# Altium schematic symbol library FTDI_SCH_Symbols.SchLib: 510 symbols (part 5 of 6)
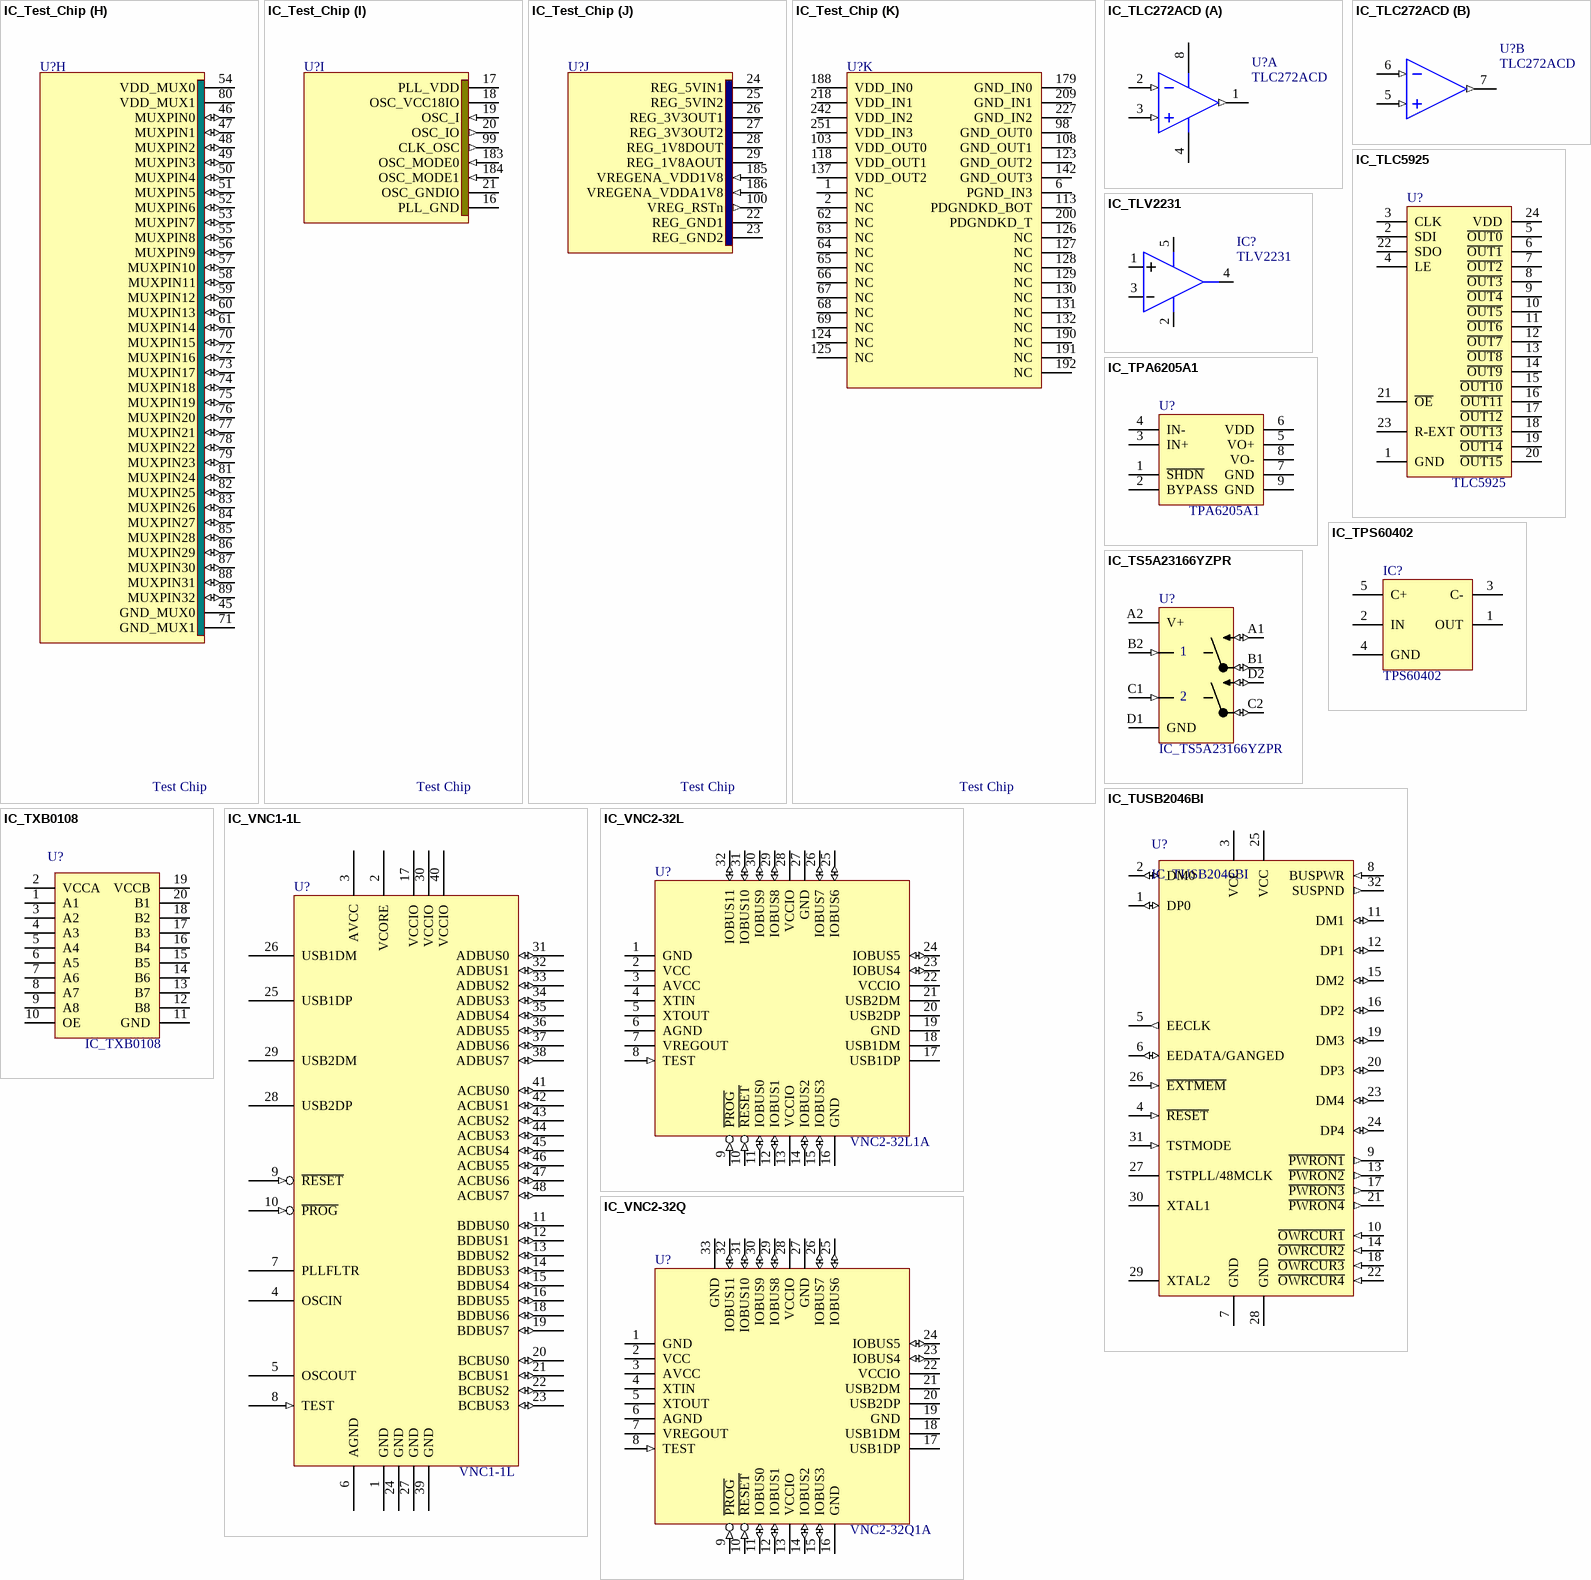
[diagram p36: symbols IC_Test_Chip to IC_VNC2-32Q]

## IC_Test_Chip
designator U?, comment Test Chip
part A pins: 97 SCAN_MODE, 181 CLK_SYS, 182 RST#
part B pins: 90 GND_USB110_L (power), 91 USB1_DP (io), 92 USB1_DM (io), 93 VCCUSB110_SH (power), 94 USB0_DP (io), 95 USB0_DM (io), 96 GNDUSB110_R (power)
part C pins: 30 VDD_USB230_T (power), 31 GND_USB230_T (power), 32 USB230_XSCI (in), 33 USB230_XSCO (out), 34 USB230_VCCHSRT1 (power), 35 USB230_VCCHSRT2 (power), 36 USB230_GNDHSRT1 (power), 37 USB230_GNDHSRT2 (power), 38 USB230_RREF (in), 39 USB230_DM (io), 40 USB230_DP (io), 41 USB230_VCCA_U20 (power), 42 USB230_GNDA_U20 (power), 43 GND_USB230_B (power), 44 VCC_USB230_B (power), 140 USBHS_CLKOUT (out), 141 USBHS_TXREADY (out), 143 USBHS_RXVALID (out), 144 USBHS_RXACTIVE (out), 145 USBHS_RXERR (out), 146 USBHS_HOSTDISC (out), 147 USBHS_PORSIG (out), 187 USB_HS_SEL (in)
part D pins: 101 EE_DONEX (out), 102 EE_DOX0 (out), 104 EE_DOX1 (out), 105 EE_DOX2 (out), 106 EE_DOX3 (out), 107 EE_DOX4 (out), 109 EE_DOX5 (out), 110 EE_DOX6 (out), 111 EE_DOX7 (out), 112 EE_DOX8 (out), 114 EE_DOX9 (out), 115 EE_DOX10 (out), 116 EE_DOX11 (out), 189 EE_SEL (in), 193 EE_CLKX (in), 194 EE_MODEX0 (in), 195 EE_MODEX1 (in), 196 EE_MODEX2 (in), 197 EE_GOX (in), 198 EE_EXTENDX (in), 199 EE_RSTNX (in), 201 EE_PAGE_ADDRX0 (in), 202 EE_PAGE_ADDRX1 (in), 203 EE_PAGE_ADDRX2 (in), 204 EE_PAGE_ADDRX3 (in), 205 EE_PAGE_ADDRX4 (in), 206 EE_PAGE_ADDRX5 (in), 207 EE_PAGE_ADDRX6 (in), 208 EE_BYTE_ADDRX0 (in), 210 EE_BYTE_ADDRX1 (in), 211 EE_BIT_ADDRX0 (in), 212 EE_BIT_ADDRX1 (in), 213 EE_BIT_ADDRX2 (in), 214 EE_BIT_ADDRX3 (in), 215 EE_DINX (in), 216 EE_SA_BIAS0 (in), 217 EE_SA_BIAS1 (in), 219 EE_SA_BIAS2 (in), 220 EE_SA_BIAS3 (in), 221 EE_SA_BIAS_ONX (in), 228 VPP_EE0, 229 VDD3V3_EE0, 230 VDD1V8_EE0, 239 GND_EE, 240 VDD3V3_EE1, 241 VDD1V8_EE1
part E pins: 3 HADDR7 (in), 4 HWD0 (in), 5 HWD1 (in), 7 HWD2 (in), 8 HWD3 (in), 9 HWD4 (in), 10 HWD5 (in), 11 HWD6 (in), 12 HWD7 (in), 13 HWRITE (in), 14 HREADY (in), 15 HSEL_IOCTRL (in), 121 HRD0 (in), 122 HRD1 (in), 133 HRD2 (in), 134 HRD3 (in), 135 HRD4 (in), 136 HRD5 (in), 138 HRD6 (in), 139 HRD7 (in), 180 HSEL_PADCTRL (in), 249 HADDR0 (in), 250 HADDR1 (in), 252 HADDR2 (in), 253 HADDR3 (in), 254 HADDR4 (in), 255 HADDR5 (in), 256 HADDR6 (in)
part F pins: 120 IOCELLCONTR_INT, 148 IOPBOND0 (io), 149 IOPBOND1 (io), 150 IOPBOND2 (io), 151 IOPBOND3 (io), 152 GND_PADUNI2 (power), 153 IOPBOND4 (io), 154 IOPBOND5 (io), 155 IOPBOND6 (io), 156 IOPBOND7 (io), 157 VDD_PADUNI2 (power), 158 IOPBOND8 (io), 159 IOPBOND9 (io), 160 IOPBOND10 (io), 161 IOPBOND11 (io), 162 GND_PADUNI1 (power), 163 IOPBOND12 (io), 164 IOPBOND13 (io), 165 IOPBOND14 (io), 166 IOPBOND15 (io), 167 VDD_PADUNI1 (power), 168 IOPBOND16 (io), 169 IOPBOND17 (io), 170 IOPBOND18 (io), 171 IOPBOND19 (io), 172 GND_PADUNI0 (power), 173 IOPBOND20 (io), 174 IOPBOND21 (io), 175 IOPBOND22 (io), 176 IOPBOND23 (io), 177 VDD_PADUNI0 (power), 178 IOBOND_SINGLE (io)
part G pins: 117 IOP_SINGLE_DIN (out), 119 IOP_SINGLE_CMPOUT (out), 222 IOP_SINGLE_DAC_D0 (in), 223 IOP_SINGLE_DAC_D1 (in), 224 IOP_SINGLE_DAC_D2 (in), 225 IOP_SINGLE_DAC_D3 (in), 226 IOP_SINGLE_DAC_D4 (in), 231 IOP_SINGLE_DAC_D5 (in), 232 IOP_SINGLE_DAC_D6 (in), 233 IOP_SINGLE_DAC_D7 (in), 234 IOP_SINGLE_DAC_D8 (in), 235 IOP_SINGLE_DAC_D9 (in), 236 IOP_SINGLE_DOUT (in), 237 IOP_SINGLE_DMODE0 (in), 238 IOP_SINGLE_DMODE1 (in), 243 IOP_SINGLE_DIENA (in), 244 IOP_SINGLE_PUENAn (in), 245 IOP_SINGLE_PDENA (in), 246 IOP_SINGLE_SAMPLE (in), 247 IOP_SINGLE_AMODE0 (in), 248 IOP_SINGLE_AMODE1 (in)
part H pins: 45 GND_MUX0 (power), 46 MUXPIN0 (io), 47 MUXPIN1 (io), 48 MUXPIN2 (io), 49 MUXPIN3 (io), 50 MUXPIN4 (io), 51 MUXPIN5 (io), 52 MUXPIN6 (io), 53 MUXPIN7 (io), 54 VDD_MUX0 (power), 55 MUXPIN8 (io), 56 MUXPIN9 (io), 57 MUXPIN10 (io), 58 MUXPIN11 (io), 59 MUXPIN12 (io), 60 MUXPIN13 (io), 61 MUXPIN14 (io), 70 MUXPIN15 (io), 71 GND_MUX1 (power), 72 MUXPIN16 (io), 73 MUXPIN17 (io), 74 MUXPIN18 (io), 75 MUXPIN19 (io), 76 MUXPIN20 (io), 77 MUXPIN21 (io), 78 MUXPIN22 (io), 79 MUXPIN23 (io), 80 VDD_MUX1 (power), 81 MUXPIN24 (io), 82 MUXPIN25 (io), 83 MUXPIN26 (io), 84 MUXPIN27 (io), 85 MUXPIN28 (io), 86 MUXPIN29 (io), 87 MUXPIN30 (io), 88 MUXPIN31 (io), 89 MUXPIN32 (io)
part I pins: 16 PLL_GND (power), 17 PLL_VDD (power), 18 OSC_VCC18IO (power), 19 OSC_I (in), 20 OSC_IO (out), 21 OSC_GNDIO (power), 99 CLK_OSC (out), 183 OSC_MODE0 (in), 184 OSC_MODE1 (in)
part J pins: 22 REG_GND1 (power), 23 REG_GND2 (power), 24 REG_5VIN1 (power), 25 REG_5VIN2 (power), 26 REG_3V3OUT1 (power), 27 REG_3V3OUT2 (power), 28 REG_1V8DOUT (power), 29 REG_1V8AOUT (power), 100 VREG_RSTn (out), 185 VREGENA_VDD1V8 (in), 186 VREGENA_VDDA1V8 (in)
part K pins: 1 NC, 2 NC, 6 PGND_IN3 (power), 62 NC, 63 NC, 64 NC, 65 NC, 66 NC, 67 NC, 68 NC, 69 NC, 98 GND_OUT0 (power), 103 VDD_OUT0 (power), 108 GND_OUT1 (power), 113 PDGNDKD_BOT (power), 118 VDD_OUT1 (power), 123 GND_OUT2 (power), 124 NC, 125 NC, 126 NC, 127 NC, 128 NC, 129 NC, 130 NC, 131 NC, 132 NC, 137 VDD_OUT2 (power), 142 GND_OUT3 (power), 179 GND_IN0, 188 VDD_IN0 (power), 190 NC, 191 NC, 192 NC, 200 PDGNDKD_T (power), 209 GND_IN1 (power), 218 VDD_IN1 (power), 227 GND_IN2 (power), 242 VDD_IN2 (power), 251 VDD_IN3 (power)

## IC_TLC272ACD
designator U?, comment TLC272ACD
LinCMOS Precision Dual Operational Amplifier
3D model D008 (8-Pin Small Outline Integrated Circuit 1.27 mm Pitch)
footprint SO-8_N (8-Pin Small Outline Integrated Circuit 1.27 mm Pitch, IPC Medium Density)
part A pins: 1 OUT (out), 2 IN- (in), 3 IN+ (in), 4 VDD-, 8 VDD+
part B pins: 5 IN+ (in), 6 IN- (in), 7 OUT (out)

## IC_TLC5925
designator U?, comment TLC5925
LOW-POWER 16-CHANNEL CONSTANT-CURRENT LED SINK DRIVER
footprint SO-24N (SOIC, 24-Leads, Body 15.4x7.5mm, Pitch 1.27mm, IPC Medium Density)
footprint TSOP65P640X120-24N (TSOP, 24-Leads, Body 7.9x4.5mm (max), Pitch 0.65mm, IPC Medium Density)
pins: 1 GND, 2 SDI, 3 CLK, 4 LE, 5 ~{OUT0}, 6 ~{OUT1}, 7 ~{OUT2}, 8 ~{OUT3}, 9 ~{OUT4}, 10 ~{OUT5}, 11 ~{OUT6}, 12 ~{OUT7}, 13 ~{OUT8}, 14 ~{OUT9}, 15 ~{OUT10}, 16 ~{OUT11}, 17 ~{OUT12}, 18 ~{OUT13}, 19 ~{OUT14}, 20 ~{OUT15}, 21 ~{OE}, 22 SDO, 23 R-EXT, 24 VDD

## IC_TLV2231
designator IC?, comment TLV2231
Single operational amplifier
footprint SOT23-5AL (SOT23, 5-Leads, Body 2.9x1.6mm, Pitch 0.95mm, Lead Span 2.8mm, IPC High Density)
pins: 1 IN+, 2 V-, 3 IN-, 4 OUT, 5 V+

## IC_TPA6205A1
designator U?, comment TPA6205A1
IC AMP AUDIO PWR 1.25W AB 8MSOP; ManufacturerPartNo: TPA6205A1DGNR; Manufacturer: TI
footprint PSO06531x505-8N
pins: 1 ~{SHDN}, 2 BYPASS, 3 IN+, 4 IN-, 5 VO+, 6 VDD, 7 GND, 8 VO-, 9 GND

## IC_TPS60402
designator IC?, comment TPS60402
Voltage inverter
footprint SOT23-5AL (SOT23, 5-Leads, Body 2.9x1.6mm, Pitch 0.95mm, Lead Span 2.8mm, IPC High Density)
pins: 1 OUT, 2 IN, 3 C-, 4 GND (power), 5 C+

## IC_TS5A23166YZPR
designator U?
0.9-OHM 5-V/3.3-V 2-CHANNEL ANALOG SWITCH
footprint BGA8C50P4X2_190X90X50 (BGA, 8-Leads, Body 1.9x0.9mm,  Pitch 0.50mm)
pins: A1 NO1 (io), A2 V+ (power), B1 COM1 (io), B2 IN1 (in), C1 IN2 (in), C2 COM2 (io), D1 GND (power), D2 NO2 (io)

## IC_TUSB2046BI
designator U?
4 Port USB HUB
footprint TQFP80P900X900X160-32N (TQFP, 32-Leads, Body 9.2x9.2mm (max), Pitch 0.80mm, IPC Medium Density)
pins: 1 DP0 (io), 2 DM0 (io), 3 VCC (power), 4 ~{RESET} (in), 5 EECLK (out), 6 EEDATA/GANGED (io), 7 GND (power), 8 BUSPWR (in), 9 ~{PWRON1} (out), 10 ~{OWRCUR1} (in), 11 DM1 (io), 12 DP1 (io), 13 ~{PWRON2} (out), 14 ~{OWRCUR2} (in), 15 DM2 (io), 16 DP2 (io), 17 ~{PWRON3} (out), 18 ~{OWRCUR3} (in), 19 DM3 (io), 20 DP3 (io), 21 ~{PWRON4} (out), 22 ~{OWRCUR4} (in), 23 DM4 (io), 24 DP4 (io), 25 VCC (power), 26 ~{EXTMEM} (in), 27 TSTPLL/48MCLK, 28 GND (power), 29 XTAL2, 30 XTAL1, 31 TSTMODE (in), 32 SUSPND (out)

## IC_TXB0108
designator U?
8-BIT BIDIRECTIONAL VOLTAGE-LEVEL TRANSLATOR  WITH AUTO-DIRECTION SENSING AND ±15-kV ESD PROTECTION
footprint TSOP65P640X120-20N (TSOP, 20-Leads, Body 6.6x4.5mm (max), Pitch 0.65mm, IPC Medium Density)
pins: 1 A1, 2 VCCA, 3 A2, 4 A3, 5 A4, 6 A5, 7 A6, 8 A7, 9 A8, 10 OE, 11 GND, 12 B8, 13 B7, 14 B6, 15 B5, 16 B4, 17 B3, 18 B2, 19 VCCB, 20 B1

## IC_VNC1-1L
designator U?, comment VNC1-1L
footprint LQFP-48_N (48-Pin Thin Quad Flat Pack 0.5 mm Pitch, IPC Medium Density)
pins: 1 GND (power), 2 VCORE (power), 3 AVCC (power), 4 OSCIN, 5 OSCOUT, 6 AGND (power), 7 PLLFLTR, 8 TEST (in), 9 ~{RESET} (in), 10 ~{PROG} (in), 11 BDBUS0 (io), 12 BDBUS1 (io), 13 BDBUS2 (io), 14 BDBUS3 (io), 15 BDBUS4 (io), 16 BDBUS5 (io), 17 VCCIO (power), 18 BDBUS6 (io), 19 BDBUS7 (io), 20 BCBUS0 (io), 21 BCBUS1 (io), 22 BCBUS2 (io), 23 BCBUS3 (io), 24 GND (power), 25 USB1DP, 26 USB1DM, 27 GND (power), 28 USB2DP, 29 USB2DM, 30 VCCIO (power), 31 ADBUS0 (io), 32 ADBUS1 (io), 33 ADBUS2 (io), 34 ADBUS3 (io), 35 ADBUS4 (io), 36 ADBUS5 (io), 37 ADBUS6 (io), 38 ADBUS7 (io), 39 GND (power), 40 VCCIO (power), 41 ACBUS0 (io), 42 ACBUS1 (io), 43 ACBUS2 (io), 44 ACBUS3 (io), 45 ACBUS4 (io), 46 ACBUS5 (io), 47 ACBUS6 (io), 48 ACBUS7 (io)

## IC_VNC2-32L
designator U?, comment VNC2-32L1A
Vinculum-II Embedded USB Host Controller IC; 32 pin LQFP
footprint LQFP-32_N (32-Pin Thin Quad Flat Pack 0.8 mm Pitch, IPC Medium Density)
pins: 1 GND (power), 2 VCC (power), 3 AVCC (power), 4 XTIN, 5 XTOUT, 6 AGND (power), 7 VREGOUT (power), 8 TEST (in), 9 ~{PROG} (in), 10 ~{RESET} (in), 11 IOBUS0 (io), 12 IOBUS1 (io), 13 VCCIO (power), 14 IOBUS2 (io), 15 IOBUS3 (io), 16 GND (power), 17 USB1DP, 18 USB1DM, 19 GND (power), 20 USB2DP, 21 USB2DM, 22 VCCIO (power), 23 IOBUS4 (io), 24 IOBUS5 (io), 25 IOBUS6 (io), 26 IOBUS7 (io), 27 GND (power), 28 VCCIO (power), 29 IOBUS8 (io), 30 IOBUS9 (io), 31 IOBUS10 (io), 32 IOBUS11 (io)

## IC_VNC2-32Q
designator U?, comment VNC2-32Q1A
Vinculum-II Embedded USB Host Controller IC; 32 pin QFN
footprint QFN32_N (32-Pin Quad Flat No-Lead 0.5 mm Pitch, IPC Medium Density)
pins: 1 GND (power), 2 VCC (power), 3 AVCC (power), 4 XTIN, 5 XTOUT, 6 AGND (power), 7 VREGOUT (power), 8 TEST (in), 9 ~{PROG} (in), 10 ~{RESET} (in), 11 IOBUS0 (io), 12 IOBUS1 (io), 13 VCCIO (power), 14 IOBUS2 (io), 15 IOBUS3 (io), 16 GND (power), 17 USB1DP, 18 USB1DM, 19 GND (power), 20 USB2DP, 21 USB2DM, 22 VCCIO (power), 23 IOBUS4 (io), 24 IOBUS5 (io), 25 IOBUS6 (io), 26 IOBUS7 (io), 27 GND (power), 28 VCCIO (power), 29 IOBUS8 (io), 30 IOBUS9 (io), 31 IOBUS10 (io), 32 IOBUS11 (io), 33 GND (power)

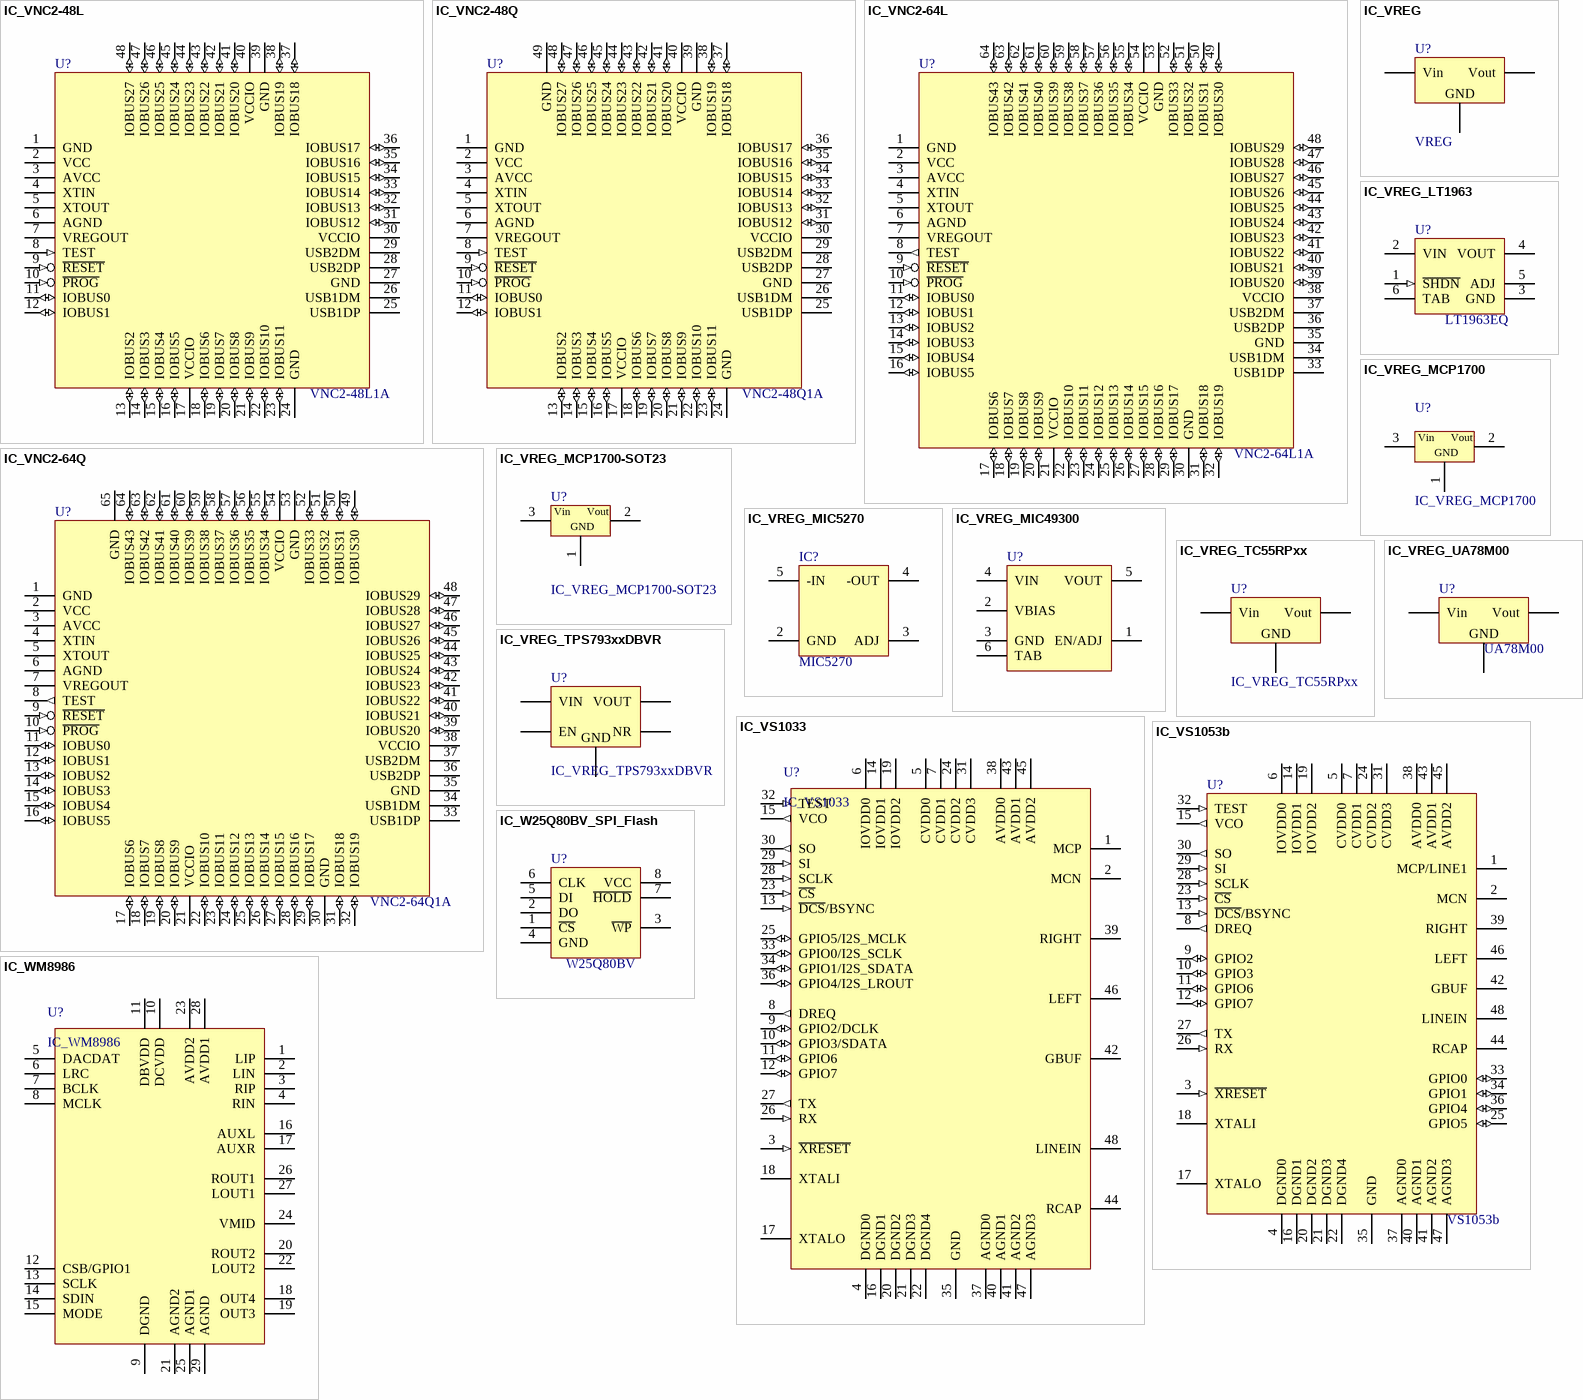
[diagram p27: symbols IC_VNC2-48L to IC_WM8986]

## IC_VNC2-48L
designator U?, comment VNC2-48L1A
Vinculum-II Embedded USB Host Controller IC; 48-pin LQFP
footprint LQFP-48_N (48-Pin Thin Quad Flat Pack 0.5 mm Pitch, IPC Medium Density)
pins: 1 GND (power), 2 VCC (power), 3 AVCC (power), 4 XTIN, 5 XTOUT, 6 AGND (power), 7 VREGOUT (power), 8 TEST (in), 9 ~{RESET} (in), 10 ~{PROG} (in), 11 IOBUS0 (io), 12 IOBUS1 (io), 13 IOBUS2 (io), 14 IOBUS3 (io), 15 IOBUS4 (io), 16 IOBUS5 (io), 17 VCCIO (power), 18 IOBUS6 (io), 19 IOBUS7 (io), 20 IOBUS8 (io), 21 IOBUS9 (io), 22 IOBUS10 (io), 23 IOBUS11 (io), 24 GND (power), 25 USB1DP, 26 USB1DM, 27 GND (power), 28 USB2DP, 29 USB2DM, 30 VCCIO (power), 31 IOBUS12 (io), 32 IOBUS13 (io), 33 IOBUS14 (io), 34 IOBUS15 (io), 35 IOBUS16 (io), 36 IOBUS17 (io), 37 IOBUS18 (io), 38 IOBUS19 (io), 39 GND (power), 40 VCCIO (power), 41 IOBUS20 (io), 42 IOBUS21 (io), 43 IOBUS22 (io), 44 IOBUS23 (io), 45 IOBUS24 (io), 46 IOBUS25 (io), 47 IOBUS26 (io), 48 IOBUS27 (io)

## IC_VNC2-48Q
designator U?, comment VNC2-48Q1A
Vinculum-II Embedded USB Host Controller IC; 48-pin QFN
footprint QFN50P800X800-48N (QFN, 48-Leads, Body 8.0x8.0mm (max), Pitch 0.50mm, IPC Medium Density)
pins: 1 GND (power), 2 VCC (power), 3 AVCC (power), 4 XTIN, 5 XTOUT, 6 AGND (power), 7 VREGOUT (power), 8 TEST (in), 9 ~{RESET} (in), 10 ~{PROG} (in), 11 IOBUS0 (io), 12 IOBUS1 (io), 13 IOBUS2 (io), 14 IOBUS3 (io), 15 IOBUS4 (io), 16 IOBUS5 (io), 17 VCCIO (power), 18 IOBUS6 (io), 19 IOBUS7 (io), 20 IOBUS8 (io), 21 IOBUS9 (io), 22 IOBUS10 (io), 23 IOBUS11 (io), 24 GND (power), 25 USB1DP, 26 USB1DM, 27 GND (power), 28 USB2DP, 29 USB2DM, 30 VCCIO (power), 31 IOBUS12 (io), 32 IOBUS13 (io), 33 IOBUS14 (io), 34 IOBUS15 (io), 35 IOBUS16 (io), 36 IOBUS17 (io), 37 IOBUS18 (io), 38 IOBUS19 (io), 39 GND (power), 40 VCCIO (power), 41 IOBUS20 (io), 42 IOBUS21 (io), 43 IOBUS22 (io), 44 IOBUS23 (io), 45 IOBUS24 (io), 46 IOBUS25 (io), 47 IOBUS26 (io), 48 IOBUS27 (io), 49 GND (power)

## IC_VNC2-64L
designator U?, comment VNC2-64L1A
Vinculum-II Embedded USB Host Controller IC; 64-pin LQFP
footprint LQFP50P10X10-64N (LQFP, 64-Leads, Body 10x10mm (max), Pitch 0.50mm, IPC Medium Density)
pins: 1 GND (power), 2 VCC (power), 3 AVCC (power), 4 XTIN, 5 XTOUT, 6 AGND (power), 7 VREGOUT (power), 8 TEST (out), 9 ~{RESET} (in), 10 ~{PROG} (in), 11 IOBUS0 (io), 12 IOBUS1 (io), 13 IOBUS2 (io), 14 IOBUS3 (io), 15 IOBUS4 (io), 16 IOBUS5 (io), 17 IOBUS6 (io), 18 IOBUS7 (io), 19 IOBUS8 (io), 20 IOBUS9 (io), 21 VCCIO (power), 22 IOBUS10 (io), 23 IOBUS11 (io), 24 IOBUS12 (io), 25 IOBUS13 (io), 26 IOBUS14 (io), 27 IOBUS15 (io), 28 IOBUS16 (io), 29 IOBUS17 (io), 30 GND (power), 31 IOBUS18 (io), 32 IOBUS19 (io), 33 USB1DP, 34 USB1DM, 35 GND (power), 36 USB2DP, 37 USB2DM, 38 VCCIO (power), 39 IOBUS20 (io), 40 IOBUS21 (io), 41 IOBUS22 (io), 42 IOBUS23 (io), 43 IOBUS24 (io), 44 IOBUS25 (io), 45 IOBUS26 (io), 46 IOBUS27 (io), 47 IOBUS28 (io), 48 IOBUS29 (io), 49 IOBUS30 (io), 50 IOBUS31 (io), 51 IOBUS32 (io), 52 IOBUS33 (io), 53 GND (power), 54 VCCIO (power), 55 IOBUS34 (io), 56 IOBUS35 (io), 57 IOBUS36 (io), 58 IOBUS37 (io), 59 IOBUS38 (io), 60 IOBUS39 (io), 61 IOBUS40 (io), 62 IOBUS41 (io), 63 IOBUS42 (io), 64 IOBUS43 (io)

## IC_VNC2-64Q
designator U?, comment VNC2-64Q1A
Vinculum-II Embedded USB Host Controller IC; 64-pin QFN
footprint QFN50P900X900-64N (QFN, 64-Leads, Body 9x9mm, Pitch 0.50mm, IPC Medium Density)
pins: 1 GND (power), 2 VCC (power), 3 AVCC (power), 4 XTIN, 5 XTOUT, 6 AGND (power), 7 VREGOUT (power), 8 TEST (out), 9 ~{RESET} (in), 10 ~{PROG} (in), 11 IOBUS0 (io), 12 IOBUS1 (io), 13 IOBUS2 (io), 14 IOBUS3 (io), 15 IOBUS4 (io), 16 IOBUS5 (io), 17 IOBUS6 (io), 18 IOBUS7 (io), 19 IOBUS8 (io), 20 IOBUS9 (io), 21 VCCIO (power), 22 IOBUS10 (io), 23 IOBUS11 (io), 24 IOBUS12 (io), 25 IOBUS13 (io), 26 IOBUS14 (io), 27 IOBUS15 (io), 28 IOBUS16 (io), 29 IOBUS17 (io), 30 GND (power), 31 IOBUS18 (io), 32 IOBUS19 (io), 33 USB1DP, 34 USB1DM, 35 GND (power), 36 USB2DP, 37 USB2DM, 38 VCCIO (power), 39 IOBUS20 (io), 40 IOBUS21 (io), 41 IOBUS22 (io), 42 IOBUS23 (io), 43 IOBUS24 (io), 44 IOBUS25 (io), 45 IOBUS26 (io), 46 IOBUS27 (io), 47 IOBUS28 (io), 48 IOBUS29 (io), 49 IOBUS30 (io), 50 IOBUS31 (io), 51 IOBUS32 (io), 52 IOBUS33 (io), 53 GND (power), 54 VCCIO (power), 55 IOBUS34 (io), 56 IOBUS35 (io), 57 IOBUS36 (io), 58 IOBUS37 (io), 59 IOBUS38 (io), 60 IOBUS39 (io), 61 IOBUS40 (io), 62 IOBUS41 (io), 63 IOBUS42 (io), 64 IOBUS43 (io), 65 GND (power)

## IC_VREG
designator U?, comment VREG
Voltage Regulator
footprint SOT223P700-4N (SOT223, 4-Leads, Body 6.5x3.5mm, Pitch 2.3mm, Lead Span 7mm, IPC Medium Density)
footprint TO228P973X240-3N (D-PAK, 3-Pads, Body 6.2x6.6mm (max), IPC Medium Density)
pins: 1 GND, 3 Vin, 4 Vout

## IC_VREG_LT1963
designator U?, comment LT1963EQ
1.5A, Low Noise,  Fast Transient Response  LDO Regulator
pins: 1 ~{SHDN} (in), 2 VIN (power), 3 GND (power), 4 VOUT (power), 5 ADJ, 6 TAB (power)

## IC_VREG_MCP1700
designator U?
LDO Vlotage Regulator
footprint SOT23-3AL (SOT23 SMT Package)
pins: 1 GND, 2 Vout, 3 Vin

## IC_VREG_MCP1700-SOT23
designator U?
Voltage Regulator
footprint SOT23-3AL (SOT23 SMT Package)
pins: 1 GND, 2 Vout, 3 Vin

## IC_VREG_MIC5270
designator IC?, comment MIC5270
footprint SOT23-5AL (SOT23, 5-Leads, Body 2.9x1.6mm, Pitch 0.95mm, Lead Span 2.8mm, IPC High Density)
pins: 2 GND (power), 3 ADJ, 4 -OUT, 5 -IN

## IC_VREG_MIC49300
designator U?
3.0A Low Voltage LDO Regulator w/Dual Input Voltages; Micrel
pins: 1 EN/ADJ, 2 VBIAS, 3 GND, 4 VIN, 5 VOUT, 6 TAB

## IC_VREG_TC55RPxx
designator U?
1uA LOW DROPOUT POSITIVE VOLTAGE REGULATOR
footprint SOT23-3AL (SOT23 SMT Package)
pins: 1 GND, 2 Vout, 3 Vin

## IC_VREG_TPS793xxDBVR
designator U?
LDO Voltage Regulator; 1.5A; DPAK-3
footprint SOT23-5AL (SOT23, 5-Leads, Body 2.9x1.6mm, Pitch 0.95mm, Lead Span 2.8mm)
pins: 1 VIN, 2 GND, 3 EN, 4 NR, 5 VOUT

## IC_VREG_UA78M00
designator U?, comment UA78M00
0.5A Voltage Regulator
footprint SOT223P700X180-4N (SOT223, 4-Leads, Body 6.7x7.3mm (max), Pitch 2.30mm, IPC Medium Density)
footprint TO252P955X203-3N (D-PAK, 3-Pads, Body 6.3x6.2mm (max), IPC Medium Density); pin to pad 2>4 4>2
pins: 1 Vin, 2 Vout, 3 GND, 4 Vout hidden

## IC_VS1033
designator U?
single-chip MP3/AAC/WMA/MIDI  audio decoder and ADPCM encoder; VLSI Solution Oy
footprint LQFP-48_N (48-Pin Thin Quad Flat Pack 0.5 mm Pitch, IPC Medium Density)
pins: 1 MCP, 2 MCN, 3 ~{XRESET} (in), 4 DGND0 (power), 5 CVDD0 (power), 6 IOVDD0 (power), 7 CVDD1 (power), 8 DREQ (out), 9 GPIO2/DCLK (io), 10 GPIO3/SDATA (io), 11 GPIO6 (io), 12 GPIO7 (io), 13 ~{DCS}/BSYNC (in), 14 IOVDD1 (power), 15 VCO (out), 16 DGND1 (power), 17 XTALO, 18 XTALI, 19 IOVDD2 (power), 20 DGND2 (power), 21 DGND3 (power), 22 DGND4 (power), 23 ~{CS} (in), 24 CVDD2 (power), 25 GPIO5/I2S_MCLK (io), 26 RX (in), 27 TX (out), 28 SCLK (in), 29 SI (in), 30 SO (out), 31 CVDD3 (power), 32 TEST (in), 33 GPIO0/I2S_SCLK (io), 34 GPIO1/I2S_SDATA (io), 35 GND (power), 36 GPIO4/I2S_LROUT (io), 37 AGND0 (power), 38 AVDD0 (power), 39 RIGHT, 40 AGND1 (power), 41 AGND2 (power), 42 GBUF, 43 AVDD1 (power), 44 RCAP, 45 AVDD2 (power), 46 LEFT, 47 AGND3 (power), 48 LINEIN

## IC_VS1053b
designator U?, comment VS1053b
Single-chip Ogg Vorbis/MP3/AAC/-  WMA/MIDI audio decoder and an IMA ADPCM  and user-loadable Ogg Vorbis encoder.; VLSI Solution Oy
footprint LQFP-48_N (48-Pin Thin Quad Flat Pack 0.5 mm Pitch, IPC Medium Density)
pins: 1 MCP/LINE1, 2 MCN, 3 ~{XRESET} (in), 4 DGND0 (power), 5 CVDD0 (power), 6 IOVDD0 (power), 7 CVDD1 (power), 8 DREQ (out), 9 GPIO2 (io), 10 GPIO3 (io), 11 GPIO6 (io), 12 GPIO7 (io), 13 ~{DCS}/BSYNC (in), 14 IOVDD1 (power), 15 VCO (out), 16 DGND1 (power), 17 XTALO, 18 XTALI, 19 IOVDD2 (power), 20 DGND2 (power), 21 DGND3 (power), 22 DGND4 (power), 23 ~{CS} (in), 24 CVDD2 (power), 25 GPIO5 (io), 26 RX (in), 27 TX (out), 28 SCLK (in), 29 SI (in), 30 SO (out), 31 CVDD3 (power), 32 TEST (in), 33 GPIO0 (io), 34 GPIO1 (io), 35 GND (power), 36 GPIO4 (io), 37 AGND0 (power), 38 AVDD0 (power), 39 RIGHT, 40 AGND1 (power), 41 AGND2 (power), 42 GBUF, 43 AVDD1 (power), 44 RCAP, 45 AVDD2 (power), 46 LEFT, 47 AGND3 (power), 48 LINEIN

## IC_W25Q80BV_SPI_Flash
designator U?, comment W25Q80BV
8MBit Serial Flash Memory with Dual/Quad SPI
pins: 1 ~{CS}, 2 DO, 3 ~{WP}, 4 GND, 5 DI, 6 CLK, 7 ~{HOLD}, 8 VCC

## IC_WM8986
designator U?
Low Power, High Quality, Stereo DAC with rich feature
footprint QFN45P400X400X77-28N (QFN, 28-Leads, Body 4.1x4.1mm (max), Pitch 0.45mm, IPC Medium Density)
pins: 1 LIP, 2 LIN, 3 RIP, 4 RIN, 5 DACDAT, 6 LRC, 7 BCLK, 8 MCLK, 9 DGND, 10 DCVDD, 11 DBVDD, 12 CSB/GPIO1, 13 SCLK, 14 SDIN, 15 MODE, 16 AUXL, 17 AUXR, 18 OUT4, 19 OUT3, 20 ROUT2, 21 AGND2, 22 LOUT2, 23 AVDD2, 24 VMID, 25 AGND1, 26 ROUT1, 27 LOUT1, 28 AVDD1, 29 AGND

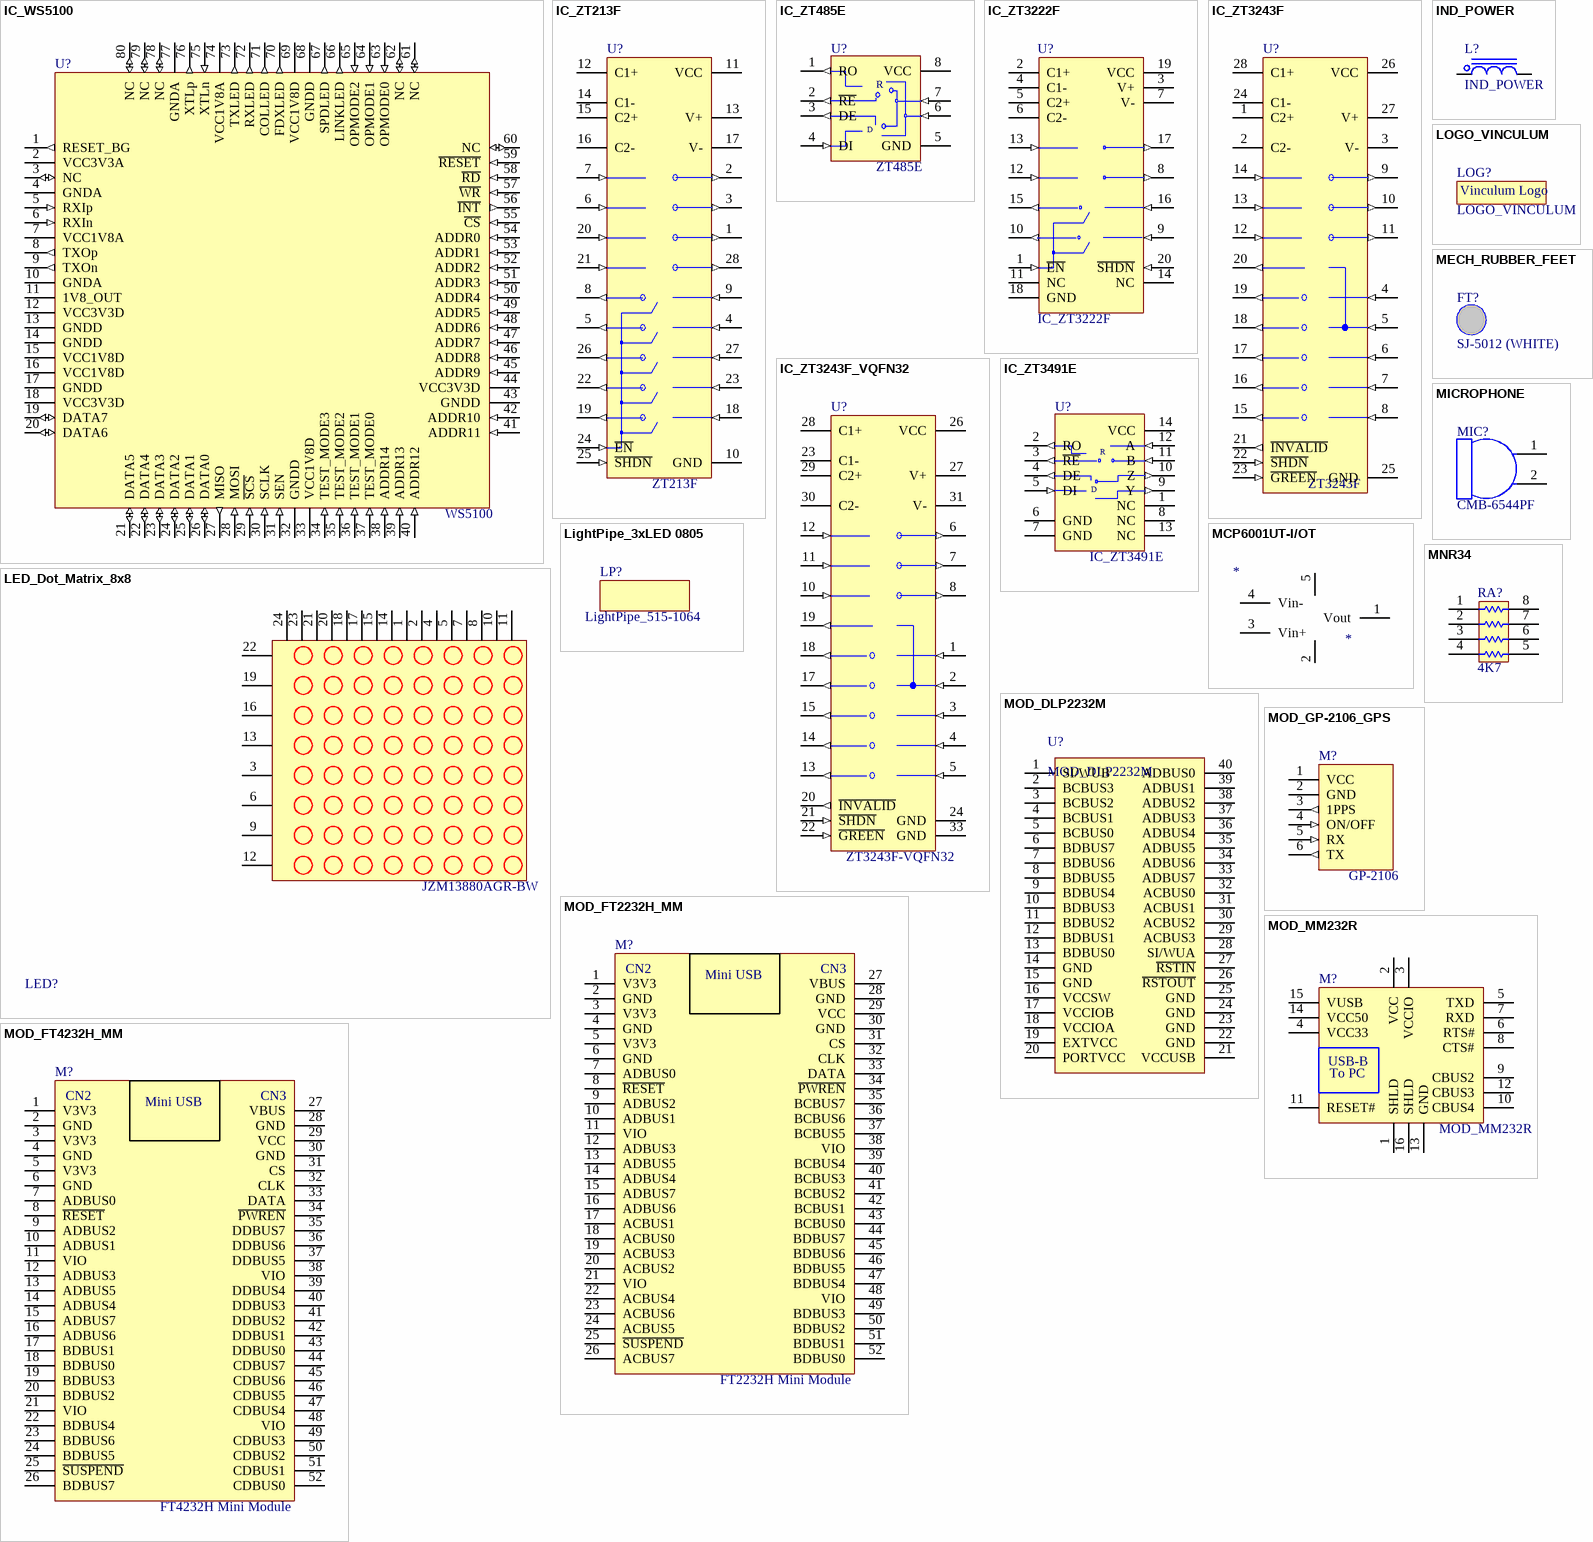
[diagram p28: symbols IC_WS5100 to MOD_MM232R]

## IC_WS5100
designator U?, comment WS5100
single-chip Internet-enabled 10/100 Ethernet controller
pins: 1 RESET_BG (out), 2 VCC3V3A (power), 3 NC (io), 4 GNDA (power), 5 RXIp (in), 6 RXIn (in), 7 VCC1V8A (power), 8 TXOp (out), 9 TXOn (out), 10 GNDA (power), 11 1V8_OUT (power), 12 VCC3V3D (power), 13 GNDD (power), 14 GNDD (power), 15 VCC1V8D (power), 16 VCC1V8D (power), 17 GNDD (power), 18 VCC3V3D (power), 19 DATA7 (io), 20 DATA6 (io), 21 DATA5 (io), 22 DATA4 (io), 23 DATA3 (io), 24 DATA2 (io), 25 DATA1 (io), 26 DATA0 (io), 27 MISO (out), 28 MOSI (in), 29 ~{SCS} (in), 30 SCLK (in), 31 SEN (in), 32 GNDD (power), 33 VCC1V8D (power), 34 TEST_MODE3 (in), 35 TEST_MODE2 (in), 36 TEST_MODE1 (in), 37 TEST_MODE0 (in), 38 ADDR14 (in), 39 ADDR13 (in), 40 ADDR12 (in), 41 ADDR11 (in), 42 ADDR10 (in), 43 GNDD (power), 44 VCC3V3D (power), 45 ADDR9 (in), 46 ADDR8 (in), 47 ADDR7 (in), 48 ADDR6 (in), 49 ADDR5 (in), 50 ADDR4 (in), 51 ADDR3 (in), 52 ADDR2 (in), 53 ADDR1 (in), 54 ADDR0 (in), 55 ~{CS} (in), 56 ~{INT} (out), 57 ~{WR} (in), 58 ~{RD} (in), 59 ~{RESET} (in), 60 NC (io), 61 NC (io), 62 NC (io), 63 OPMODE0 (in), 64 OPMODE1 (in), 65 OPMODE2 (in), 66 LINKLED (out), 67 SPDLED (out), 68 GNDD (power), 69 VCC1V8D (power), 70 FDXLED (out), 71 COLLED (out), 72 RXLED (out), 73 TXLED (out), 74 VCC1V8A (power), 75 XTLn (in), 76 XTLp (out), 77 GNDA (power), 78 NC (io), 79 NC (io), 80 NC (io)

## IC_ZT213F
designator U?, comment ZT213F
Low Power +3V to +5.5V, 1000kbps RS232 Transceiver; Manufacturer: Zywyn Corporation; ManufacturerPartNo: ZT213FEA; Note: Low Power 5V 1000kbps RS232 Transceiver
footprint SOP65P780-28N (SOP, 28-Leads, Body 10.2x5.3mm, Pitch 0.65mm, IPC Medium Density)
pins: 1 T3OUT (out), 2 T1OUT (out), 3 T2OUT (out), 4 R2IN (in), 5 R2OUT (out), 6 T2IN (in), 7 T1IN (in), 8 R1OUT (out), 9 R1IN (in), 10 GND (power), 11 VCC (power), 12 C1+, 13 V+ (power), 14 C1-, 15 C2+, 16 C2-, 17 V- (power), 18 R5IN (in), 19 R5OUT (out), 20 T3IN (in), 21 T4IN (in), 22 R4OUT (out), 23 R4IN (in), 24 ~{EN} (in), 25 ~{SHDN} (in), 26 R3OUT (out), 27 R3IN (in), 28 T4OUT (out)

## IC_ZT485E
designator U?, comment ZT485E
5V 10Mb RS485 transceiver
footprint SO-8_N (8-Pin Small Outline Integrated Circuit 1.27 mm Pitch, IPC Medium Density)
pins: 1 RO (out), 2 ~{RE} (out), 3 DE (out), 4 DI (in), 5 GND (power), 6 A (in), 7 B (in), 8 VCC (power)

## IC_ZT3222F
designator U?
Low Power +3V to +5.5V, 1000kbps RS232 Transceiver
pins: 1 ~{EN} (in), 2 C1+, 3 V+ (power), 4 C1-, 5 C2+, 6 C2-, 7 V- (power), 8 T2OUT (out), 9 R2IN (in), 10 R2OUT (out), 11 NC, 12 T2IN (in), 13 T1IN (in), 14 NC, 15 R1OUT (out), 16 R1IN (in), 17 T1OUT (out), 18 GND (power), 19 VCC (power), 20 ~{SHDN} (in)

## IC_ZT3243F
designator U?, comment ZT3243F
Low Power +3V to +5.5V, 1000kbps RS232 Transceiver; Manufacturer: Zywyn Corporation; ManufacturerPartNo: ZT213FEA; Note: Low Power 5V 1000kbps RS232 Transceiver
footprint SOP65P780-28N (SOP, 28-Leads, Body 10.2x5.3mm, Pitch 0.65mm, IPC Medium Density)
pins: 1 C2+, 2 C2-, 3 V- (power), 4 R1IN (in), 5 R2IN (in), 6 R3IN (in), 7 R4IN (in), 8 R5IN (in), 9 T1OUT (out), 10 T2OUT (out), 11 T3OUT (out), 12 T3IN (in), 13 T2IN (in), 14 T1IN (in), 15 R5OUT (out), 16 R4OUT (out), 17 R3OUT (out), 18 R2OUT (out), 19 R1OUT (out), 20 R2OUTB (out), 21 ~{INVALID} (out), 22 ~{SHDN} (in), 23 ~{GREEN} (in), 24 C1-, 25 GND (power), 26 VCC (power), 27 V+ (power), 28 C1+

## IC_ZT3243F_VQFN32
designator U?, comment ZT3243F-VQFN32
Low Power +3V to +5.5V, 1000kbps RS232 Transceiver; Manufacturer: Zywyn Corporation; ManufacturerPartNo: ZT213FEA; Note: Low Power 5V 1000kbps RS232 Transceiver
footprint QFN32_N (32-Pin Quad Flat No-Lead 0.5 mm Pitch, IPC Medium Density)
pins: 1 R1IN (in), 2 R2IN (in), 3 R3IN (in), 4 R4IN (in), 5 R5IN (in), 6 T1OUT (out), 7 T2OUT (out), 8 T3OUT (out), 10 T3IN (in), 11 T2IN (in), 12 T1IN (in), 13 R5OUT (out), 14 R4OUT (out), 15 R3OUT (out), 17 R2OUT (out), 18 R1OUT (out), 19 R2OUTB (out), 20 ~{INVALID} (out), 21 ~{SHDN} (in), 22 ~{GREEN} (in), 23 C1-, 24 GND (power), 26 VCC (power), 27 V+ (power), 28 C1+, 29 C2+, 30 C2-, 31 V- (power), 33 GND (power)

## IC_ZT3491E
designator U?
Low Power 3V 16Mbps RS485E Transceiver
footprint SO-14_N (14-Pin Small Outline Integrated Circuit 1.27 mm Pitch, IPC Medium Density)
pins: 1 NC, 2 RO (out), 3 ~{RE} (out), 4 DE (out), 5 DI (in), 6 GND (power), 7 GND (power), 8 NC, 9 Y (out), 10 Z (out), 11 B (in), 12 A (in), 13 NC, 14 VCC (power)

## IND_POWER
designator L?
Magnetic-Core Inductor
simulation model INDUCTOR (Inductor)
signal-integrity model Inductor Iron
footprint IND_IHLP2525CZ (Molded Inductor, 2-Leads, Body 6.9x6.5mm, IHLP2525CZ series, Vishay, IPC Medium Density)
footprint IND-8532 (8532 series Power Inductor-API Delevan)
footprint IND-CDRH127 (Sumida Power Inductor-CDRH series)
pins: 1, 2

## LED_Dot_Matrix_8x8
designator LED?, comment JZM13880AGR-BW
1.3" 32mm 8x8 Dot Matrix Alphanumeric Display; Red/Green; Common Anode
pins: 1 CG5, 2 CR5, 3 A5, 4 CG6, 5 CR6, 6 A6, 7 CG7, 8 CR7, 9 A7, 10 CG8, 11 CR8, 12 A8, 13 A4, 14 CR4, 15 CG4, 16 A3, 17 CR3, 18 CG3, 19 A2, 20 CR2, 21 CG2, 22 A1, 23 CR1, 24 CG1

## LightPipe_3xLED 0805
designator LP?, comment LightPipe_515-1064
Dialight Light Pipe; 515-1064 + 3xLED 0805
footprint LP25X3 (Light Pipe; Dialight; 515-1064; + 3xLEDs 0805 (Red, Green, Yellow))

## LOGO_VINCULUM
designator LOG?
footprint LOGO_10mm_VINCULUM
footprint LOGO_15mm_Vinculum

## MCP6001UT-I/OT
designator *
IC OPAMP 1.8V 1MHZ SNGL SOT23-5
pins: 1 Vout, 2 Vss, 3 Vin+, 4 Vin-, 5 Vdd

## MECH_RUBBER_FEET
designator FT?, comment SJ-5012 (WHITE)  (mechanical)
Self Adhesive Rubber Feet

## MICROPHONE
designator MIC?, comment CMB-6544PF
electret condenser microphone; CUI Inc.
footprint MICROPHONE_ELECTRET (CMB-6544PF; electret condenser microphone)
pins: 1 MICp, 2 MICn

## MNR34
designator RA?, comment 4K7
3216x4 Resistor Array
footprint MNR34 (3216x4 Resistor Array)
pins: 1, 2, 3, 4, 5, 6, 7, 8

## MOD_DLP2232M
designator U?
DLP Design FT2232D Module
pins: 1 SI/WUB, 2 BCBUS3, 3 BCBUS2, 4 BCBUS1, 5 BCBUS0, 6 BDBUS7, 7 BDBUS6, 8 BDBUS5, 9 BDBUS4, 10 BDBUS3, 11 BDBUS2, 12 BDBUS1, 13 BDBUS0, 14 GND, 15 GND, 16 VCCSW, 17 VCCIOB, 18 VCCIOA, 19 EXTVCC, 20 PORTVCC, 21 VCCUSB, 22 GND, 23 GND, 24 GND, 25 GND, 26 ~{RSTOUT}, 27 ~{RSTIN}, 28 SI/WUA, 29 ACBUS3, 30 ACBUS2, 31 ACBUS1, 32 ACBUS0, 33 ADBUS7, 34 ADBUS6, 35 ADBUS5, 36 ADBUS4, 37 ADBUS3, 38 ADBUS2, 39 ADBUS1, 40 ADBUS0

## MOD_FT2232H_MM
designator M?, comment FT2232H Mini Module
footprint Mini_Module
pins: 1 V3V3, 2 GND, 3 V3V3, 4 GND, 5 V3V3, 6 GND, 7 ADBUS0, 8 ~{RESET}, 9 ADBUS2, 10 ADBUS1, 11 VIO, 12 ADBUS3, 13 ADBUS5, 14 ADBUS4, 15 ADBUS7, 16 ADBUS6, 17 ACBUS1, 18 ACBUS0, 19 ACBUS3, 20 ACBUS2, 21 VIO, 22 ACBUS4, 23 ACBUS6, 24 ACBUS5, 25 ~{SUSPEND}, 26 ACBUS7, 27 VBUS, 28 GND, 29 VCC, 30 GND, 31 CS, 32 CLK, 33 DATA, 34 ~{PWREN}, 35 BCBUS7, 36 BCBUS6, 37 BCBUS5, 38 VIO, 39 BCBUS4, 40 BCBUS3, 41 BCBUS2, 42 BCBUS1, 43 BCBUS0, 44 BDBUS7, 45 BDBUS6, 46 BDBUS5, 47 BDBUS4, 48 VIO, 49 BDBUS3, 50 BDBUS2, 51 BDBUS1, 52 BDBUS0

## MOD_FT4232H_MM
designator M?, comment FT4232H Mini Module
footprint Mini_Module
pins: 1 V3V3, 2 GND, 3 V3V3, 4 GND, 5 V3V3, 6 GND, 7 ADBUS0, 8 ~{RESET}, 9 ADBUS2, 10 ADBUS1, 11 VIO, 12 ADBUS3, 13 ADBUS5, 14 ADBUS4, 15 ADBUS7, 16 ADBUS6, 17 BDBUS1, 18 BDBUS0, 19 BDBUS3, 20 BDBUS2, 21 VIO, 22 BDBUS4, 23 BDBUS6, 24 BDBUS5, 25 ~{SUSPEND}, 26 BDBUS7, 27 VBUS, 28 GND, 29 VCC, 30 GND, 31 CS, 32 CLK, 33 DATA, 34 ~{PWREN}, 35 DDBUS7, 36 DDBUS6, 37 DDBUS5, 38 VIO, 39 DDBUS4, 40 DDBUS3, 41 DDBUS2, 42 DDBUS1, 43 DDBUS0, 44 CDBUS7, 45 CDBUS6, 46 CDBUS5, 47 CDBUS4, 48 VIO, 49 CDBUS3, 50 CDBUS2, 51 CDBUS1, 52 CDBUS0

## MOD_GP-2106_GPS
designator M?, comment GP-2106
48 Channel GP-2106 SiRF IV GPS Receiver
pins: 1 VCC (power), 2 GND (power), 3 1PPS (out), 4 ON/OFF (in), 5 RX (in), 6 TX (out)

## MOD_MM232R
designator M?
FT232R Mini Evaluation Module
pins: 1 SHLD, 2 VCC, 3 VCCIO, 4 VCC33, 5 TXD, 6 RTS#, 7 RXD, 8 CTS#, 9 CBUS2, 10 CBUS4, 11 RESET#, 12 CBUS3, 13 GND, 14 VCC50, 15 VUSB, 16 SHLD

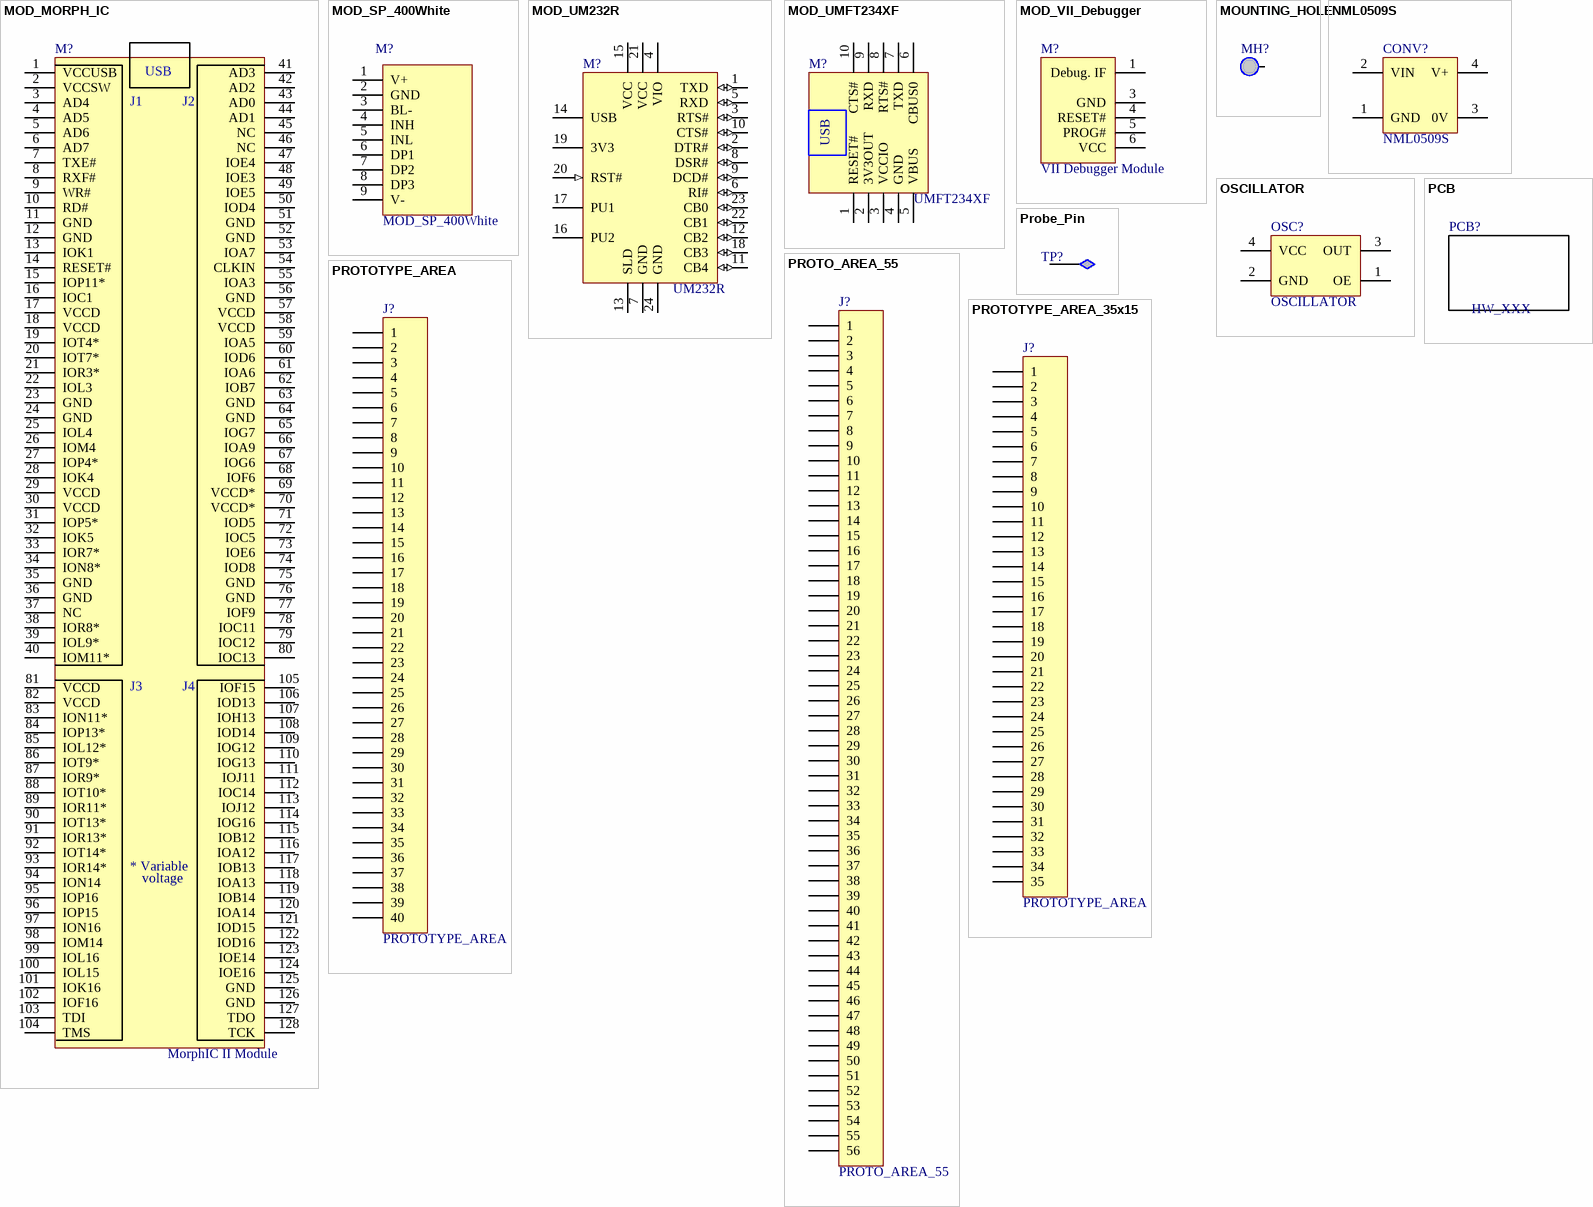
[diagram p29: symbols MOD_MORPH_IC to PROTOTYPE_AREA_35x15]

## MOD_MORPH_IC
designator M?, comment MorphIC II Module
pins: 1 VCCUSB, 2 VCCSW, 3 AD4, 4 AD5, 5 AD6, 6 AD7, 7 TXE#, 8 RXF#, 9 WR#, 10 RD#, 11 GND, 12 GND, 13 IOK1, 14 RESET#, 15 IOP11*, 16 IOC1, 17 VCCD, 18 VCCD, 19 IOT4*, 20 IOT7*, 21 IOR3*, 22 IOL3, 23 GND, 24 GND, 25 IOL4, 26 IOM4, 27 IOP4*, 28 IOK4, 29 VCCD, 30 VCCD, 31 IOP5*, 32 IOK5, 33 IOR7*, 34 ION8*, 35 GND, 36 GND, 37 NC, 38 IOR8*, 39 IOL9*, 40 IOM11*, 41 AD3, 42 AD2, 43 AD0, 44 AD1, 45 NC, 46 NC, 47 IOE4, 48 IOE3, 49 IOE5, 50 IOD4, 51 GND, 52 GND, 53 IOA7, 54 CLKIN, 55 IOA3, 56 GND, 57 VCCD, 58 VCCD, 59 IOA5, 60 IOD6, 61 IOA6, 62 IOB7, 63 GND, 64 GND, 65 IOG7, 66 IOA9, 67 IOG6, 68 IOF6, 69 VCCD*, 70 VCCD*, 71 IOD5, 72 IOC5, 73 IOE6, 74 IOD8, 75 GND, 76 GND, 77 IOF9, 78 IOC11, 79 IOC12, 80 IOC13, 81 VCCD, 82 VCCD, 83 ION11*, 84 IOP13*, 85 IOL12*, 86 IOT9*, 87 IOR9*, 88 IOT10*, 89 IOR11*, 90 IOT13*, 91 IOR13*, 92 IOT14*, 93 IOR14*, 94 ION14, 95 IOP16, 96 IOP15, 97 ION16, 98 IOM14, 99 IOL16, 100 IOL15, 101 IOK16, 102 IOF16, 103 TDI, 104 TMS, 105 IOF15, 106 IOD13, 107 IOH13, 108 IOD14, 109 IOG12, 110 IOG13, 111 IOJ11, 112 IOC14, 113 IOJ12, 114 IOG16, 115 IOB12, 116 IOA12, 117 IOB13, 118 IOA13, 119 IOB14, 120 IOA14, 121 IOD15, 122 IOD16, 123 IOE14, 124 IOE16, 125 GND, 126 GND, 127 TDO, 128 TCK

## MOD_SP_400White
designator M?
3+1/2 Digit Backlit LCD Voltmeter Module
pins: 1 V+, 2 GND, 3 BL-, 4 INH, 5 INL, 6 DP1, 7 DP2, 8 DP3, 9 V-

## MOD_UM232R
designator M?, comment UM232R
USB - Serial UART Development Module, DIL-24
pins: 1 TXD (io), 2 DTR# (io), 3 RTS# (io), 4 VIO (power), 5 RXD (io), 6 RI# (io), 7 GND (power), 8 DSR# (io), 9 DCD# (io), 10 CTS# (io), 11 CB4 (io), 12 CB2 (io), 13 SLD, 14 USB (power), 15 VCC (power), 16 PU2, 17 PU1, 18 CB3 (io), 19 3V3 (power), 20 RST# (in), 21 VCC (power), 22 CB1 (io), 23 CB0 (io), 24 GND (power)

## MOD_UMFT234XF
designator M?, comment UMFT234XF
FT232R Mini Evaluation Module
footprint UMFT234XF_Module
pins: 1 RESET#, 2 3V3OUT, 3 VCCIO, 4 GND, 5 VBUS, 6 CBUS0, 7 TXD, 8 RTS#, 9 RXD, 10 CTS#

## MOD_VII_Debugger
designator M?, comment VII Debugger Module
Vinculum II Debugger Module
footprint SIP-6-2mm (Header, 6 pin, pitch 2.0mm)
pins: 1 Debug. IF, 3 GND, 4 RESET#, 5 PROG#, 6 VCC

## MOUNTING_HOLE
designator MH?
Mouting hole
footprint MOUNTING_HOLE (3.5mm Mouting hole)
pins: 0

## NML0509S
designator CONV?
NML SERIES;  Isolated 2W Single Output DC-DC Converters
footprint NML0509S (5V/9V, Step Up, DC-DC Converter)
pins: 1 GND, 2 VIN, 3 0V, 4 V+

## OSCILLATOR
designator OSC?
Simple Clock Oscillator
footprint CRYSTAL_OSC_SMD_eCera_FD_series (eCera; FD series; 3.3V CMOS; Low Jitter; Seam Sealed Crystal Clock Oscillator; 5x3.2mm)
footprint DIP-14 (DIP; 14 Leads; Row Spacing 7.62 mm; Pitch 2.54 mm); pin to pad 2>7 3>8 4>14
footprint CRYSTAL_OSC_SMD_eCera_FJ_series (eCera; FJ series; 3.3V CMOS; Low Jitter; Seam Sealed Crystal Clock Oscillator; 2.5x2mm)
footprint CRYSTAL_OSC_SMD_eCera_FK_series (eCera; FK series; 3.3V CMOS; Low Jitter; Seam Sealed Crystal Clock Oscillator; 3.2x2.5mm)
footprint CRYSTAL_OSC_SMD_eCera_FN_series (eCera; FN series; 3.3V CMOS; Low Jitter; Seam Sealed Crystal Clock Oscillator; 7x5mm)
footprint CRYSTAL_OSC_HalfSize (DIP; 8 Leads; Row Spacing 7.62 mm; Pitch 2.54 mm)
pins: 1 OE, 2 GND, 3 OUT, 4 VCC

## PCB
designator PCB?, comment HW_XXX

## Probe_Pin
designator TP?, comment Probe Pin  (value not drawn)
Wafer Probe Card - Probe Pin
footprint TEST_PIN_PTH_MINATURE (Test pin; 1.25mm loop / 1.0mm mouting hole; Keystone; 5000-5004 and 5115-5119 series)
pins: TP

## PROTO_AREA_55
designator J?
On board prototype area 40 columns x 20 rows
footprint Prototype_Area
pins: 1, 2, 3, 4, 5, 6, 7, 8, 9, 10, 11, 12, 13, 14, 15, 16, 17, 18, 19, 20, 21, 22, 23, 24, 25, 26, 27, 28, 29, 30, 31, 32, 33, 34, 35, 36, 37, 38, 39, 40, 41, 42, 43, 44, 45, 46, 47, 48, 49, 50, 51, 52, 53, 54, 55, 56

## PROTOTYPE_AREA
designator J?
On board prototype area 40 columns x 20 rows
footprint Prototype_Area
pins: 1, 2, 3, 4, 5, 6, 7, 8, 9, 10, 11, 12, 13, 14, 15, 16, 17, 18, 19, 20, 21, 22, 23, 24, 25, 26, 27, 28, 29, 30, 31, 32, 33, 34, 35, 36, 37, 38, 39, 40

## PROTOTYPE_AREA_35x15
designator J?, comment PROTOTYPE_AREA
On board prototype area 35 columns x 15 rows
footprint Prototype_Area-34x15 (Prototype area; 34 cols x 15 rows)
pins: 1, 2, 3, 4, 5, 6, 7, 8, 9, 10, 11, 12, 13, 14, 15, 16, 17, 18, 19, 20, 21, 22, 23, 24, 25, 26, 27, 28, 29, 30, 31, 32, 33, 34, 35

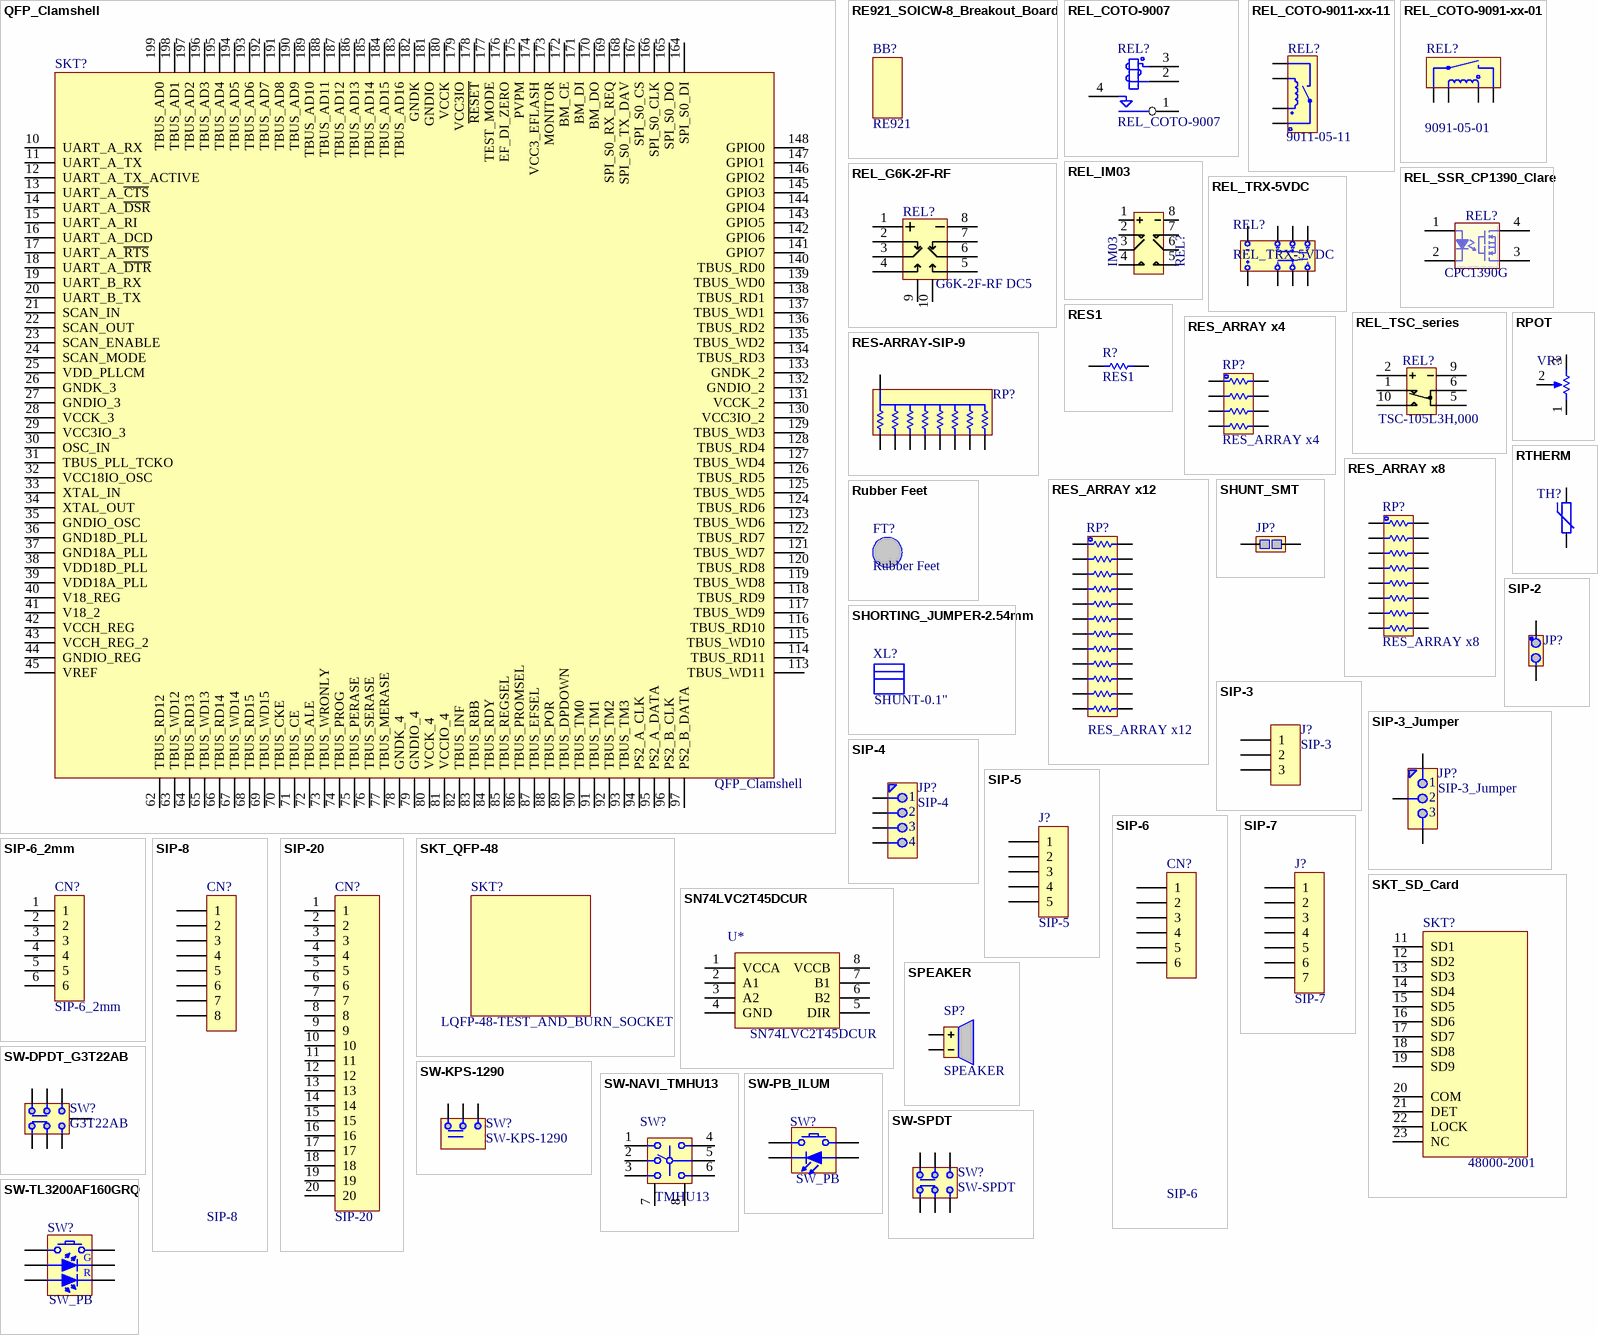
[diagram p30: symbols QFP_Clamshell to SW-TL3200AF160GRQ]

## QFP_Clamshell
designator SKT?
QFP-208 pin Clamshell
pins: 1 NC hidden, 2 NC hidden, 3 NC hidden, 4 NC hidden, 5 NC hidden, 6 NC hidden, 7 NC hidden, 8 NC hidden, 9 NC hidden, 10 UART_A_RX, 11 UART_A_TX, 12 UART_A_TX_ACTIVE, 13 UART_A_~{CTS}, 14 UART_A_~{DSR}, 15 UART_A_RI, 16 UART_A_DCD, 17 UART_A_~{RTS}, 18 UART_A_~{DTR}, 19 UART_B_RX, 20 UART_B_TX, 21 SCAN_IN, 22 SCAN_OUT, 23 SCAN_ENABLE, 24 SCAN_MODE, 25 VDD_PLLCM, 26 GNDK_3, 27 GNDIO_3, 28 VCCK_3, 29 VCC3IO_3, 30 OSC_IN, 31 TBUS_PLL_TCKO, 32 VCC18IO_OSC, 33 XTAL_IN, 34 XTAL_OUT, 35 GNDIO_OSC, 36 GND18D_PLL, 37 GND18A_PLL, 38 VDD18D_PLL, 39 VDD18A_PLL, 40 V18_REG, 41 V18_2, 42 VCCH_REG, 43 VCCH_REG_2, 44 GNDIO_REG, 45 VREF, 46 NC hidden, 47 NC hidden, 48 NC hidden, 49 NC hidden, 50 NC hidden, 51 NC hidden, 52 NC hidden, 53 NC hidden, 54 NC hidden, 55 NC hidden, 56 NC hidden, 57 NC hidden, 58 NC hidden, 59 NC hidden, 60 NC hidden, 61 NC hidden, 62 TBUS_RD12, 63 TBUS_WD12, 64 TBUS_RD13, 65 TBUS_WD13, 66 TBUS_RD14, 67 TBUS_WD14, 68 TBUS_RD15, 69 TBUS_WD15, 70 TBUS_CKE, 71 TBUS_CE, 72 TBUS_ALE, 73 TBUS_WRONLY, 74 TBUS_PROG, 75 TBUS_PERASE, 76 TBUS_SERASE, 77 TBUS_MERASE, 78 GNDK_4, 79 GNDIO_4, 80 VCCK_4, 81 VCCIO_4, 82 TBUS_INF, 83 TBUS_RBB, 84 TBUS_RDY, 85 TBUS_REGSEL, 86 TBUS_PROMSEL, 87 TBUS_EFSEL, 88 TBUS_POR, 89 TBUS_DPDOWN, 90 TBUS_TM0, 91 TBUS_TM1, 92 TBUS_TM2, 93 TBUS_TM3, 94 PS2_A_CLK, 95 PS2_A_DATA, 96 PS2_B_CLK, 97 PS2_B_DATA, 98 NC hidden, 99 NC hidden, 100 NC hidden, 101 NC hidden, 102 NC hidden, 103 NC hidden, 104 NC hidden, 105 NC hidden, 106 NC hidden, 107 NC hidden, 108 NC hidden, 109 NC hidden, 110 NC hidden, 111 NC hidden, 112 NC hidden, 113 TBUS_WD11, 114 TBUS_RD11, 115 TBUS_WD10, 116 TBUS_RD10, 117 TBUS_WD9, 118 TBUS_RD9, 119 TBUS_WD8, 120 TBUS_RD8, 121 TBUS_WD7, 122 TBUS_RD7, 123 TBUS_WD6, 124 TBUS_RD6, 125 TBUS_WD5, 126 TBUS_RD5, 127 TBUS_WD4, 128 TBUS_RD4, 129 TBUS_WD3, 130 VCC3IO_2, 131 VCCK_2, 132 GNDIO_2, 133 GNDK_2, 134 TBUS_RD3, 135 TBUS_WD2, 136 TBUS_RD2, 137 TBUS_WD1, 138 TBUS_RD1, 139 TBUS_WD0, 140 TBUS_RD0, 141 GPIO7, 142 GPIO6, 143 GPIO5, 144 GPIO4, 145 GPIO3, 146 GPIO2, 147 GPIO1, 148 GPIO0, 149 NC hidden, 150 NC hidden, 151 NC hidden, 152 NC hidden, 153 NC hidden, 154 NC hidden, 155 NC hidden, 156 NC hidden, 157 NC hidden, 158 NC hidden, 159 NC hidden, 160 NC hidden, 161 NC hidden, 162 NC hidden, 163 NC hidden, 164 SPI_S0_DI, 165 SPI_S0_DO, 166 SPI_S0_CLK, 167 SPI_S0_CS, 168 SPI_S0_TX_DAV, 169 SPI_S0_RX_REQ, 170 BM_DO, 171 BM_DI, 172 BM_CE, 173 MONITOR, 174 VCC3_EFLASH, 175 PVPM, 176 EF_DI_ZERO, 177 TEST_MODE, 178 ~{RESET}, 179 VCC3IO, 180 VCCK, 181 GNDIO, 182 GNDK, 183 TBUS_AD16, 184 TBUS_AD15, 185 TBUS_AD14, 186 TBUS_AD13, 187 TBUS_AD12, 188 TBUS_AD11, 189 TBUS_AD10, 190 TBUS_AD9, 191 TBUS_AD8, 192 TBUS_AD7, 193 TBUS_AD6, 194 TBUS_AD5, 195 TBUS_AD4, 196 TBUS_AD3, 197 TBUS_AD2, 198 TBUS_AD1, 199 TBUS_AD0, 200 NC hidden, 201 NC hidden, 202 NC hidden, 203 NC hidden, 204 NC hidden, 205 NC hidden, 206 NC hidden, 207 NC hidden, 208 NC hidden

## RE921_SOICW-8_Breakout_Board
designator BB?, comment RE921  (mechanical)
SOICW-8 Breakout Board; Roth-Electronic

## REL_COTO-9007
designator REL?
9000 Series/Spartan SIP Reed Relays with build-in diode
footprint COTO9007 (Miniature SIP Relay on 150mil pitch)
pins: 1, 2, 3, 4

## REL_COTO-9011-xx-11
designator REL?, comment 9011-05-11
9000 Series/Spartan SIP Reed Relays with build-in diode
footprint REL_COTO-9011-05-11 (Miniature SIP Relay on 100mil pitch)
pins: 1, 2, 3, 4

## REL_COTO-9091-xx-01
designator REL?, comment 9091-05-01
9000 Series/Spartan SIP Reed Relays with build-in diode
footprint COTO9007 (Miniature SIP Relay on 150mil pitch)
pins: 1, 2, 3, 4

## REL_G6K-2F-RF
designator REL?, comment G6K-2F-RF DC5
High Frequency Relay
footprint REL_G6K-2F-RF (High Frequency Relay; Omron)
pins: 1 + (power), 2, 3, 4, 5, 6, 7, 8 - (power), 9 (power), 10 (power)

## REL_IM03
designator REL?, comment IM03
Signal Relay; DPDT 2A 5V; TE Connectivity - Axicom
footprint REL_IM03GR (High Frequency Relay; Omron)
footprint REL_IM03NS (Signal Relay, Narrow version; Axicom - TE Connectivity)
pins: 1 + (power), 2 NC1, 3 COM1, 4 NO1, 5 NO2, 6 COM2, 7 NC2, 8 - (power)

## REL_SSR_CP1390_Clare
designator REL?, comment CPC1390G
Single Pole, Normally Open  4-Pin OptoMOS® Relay
footprint REL_CP1390 (Single Pole, Normally Open  4-Pin OptoMOS® Relay)
pins: 1, 2, 3, 4

## REL_TRX-5VDC
designator REL?
Tai-Shing Electronic Components Corp. 5V DIP Relay
footprint REL_TRX (DIL Relay; Tai-Shing)
pins: 1 +, 3 N.C., 4 COM, 5 N.O., 6 N.O., 7 COM, 8 N.C., 10 -

## REL_TSC_series
designator REL?, comment TSC-105L3H,000
RELAY TELECOM SPDT 1A 5V; TE Connectivity
footprint Relay_G6K-2F-RF-S (High Frequency Relay)
pins: 1, 2 + (power), 5, 6, 9 - (power), 10

## RES1
designator R?
Resistor
footprint AXIAL-0.4
footprint RESC1608-0603 (Chip Resistor; Body 1.6 x 0.8 mm (LxW typ))
footprint RESC2012-0805 (Chip Resistor; Body 2 x 1.3 mm (LxW typ))
footprint RESC3216-1206 (Chip Resistor; Body 3.2 x 1.6 mm (LxW typ))
pins: 1, 2

## RES-ARRAY-SIP-9
designator RP?
Resistor array SIP-9
footprint SIP-9 (Resistor array)
pins: 1, 2, 3, 4, 5, 6, 7, 8, 9

## RES_ARRAY x4
designator RP?
Resistor array 3216 x 4
footprint MNR34 (3216x4 Resistor Array)
footprint RESARRAY-EXBV8V (EXBV8 Series Resistor Array, 4x0603, Isolated; Panasonic)
footprint RES_ARRAY_4X0603
pins: 1, 2, 3, 4, 5, 6, 7, 8

## RES_ARRAY x8
designator RP?
Resistor array EXB2HV-Panasonic, 8x0402
footprint EXB2HV_Res_Network (Chip Resistor network, 16-Leads, Body 1.6x3.8mm, IPC Medium Density)
pins: 1, 2, 3, 4, 5, 6, 7, 8, 9, 10, 11, 12, 13, 14, 15, 16

## RES_ARRAY x12
designator RP?
Resistor array VSSR-xxxx Vishay
footprint EXB2HV_Res_Network (Chip Resistor network, 16-Leads, Body 1.6x3.8mm, IPC Medium Density)
pins: 1, 2, 3, 4, 5, 6, 7, 8, 9, 10, 11, 12, 13, 14, 15, 16, 17, 18, 19, 20, 21, 22, 23, 24

## RPOT
designator VR?
Potentiometer
footprint Pot-3266W (Potentiometer)
footprint POT-PV37_Series (Potentiometer; Multiturn-12; PV37 series; Murata)
pins: 1, 2, 3

## RTHERM
designator TH?
Thermistor
footprint Pot-3266W (Potentiometer)
footprint POT-PV37_Series (Potentiometer; Multiturn-12; PV37 series; Murata)
pins: 1, 2

## Rubber Feet
designator FT?  (mechanical)
Self ahesive rubber feet; Manufacturer: 3M; ManufacturerPartNo: SJ-5003 (WHITE); Note: BUMPON HEMISPHERE .44X.20 WHITE

## SHORTING_JUMPER-2.54mm
designator XL?, comment SHUNT-0.1"  (mechanical)
2.54mm Shorting Jumper

## SHUNT_SMT
designator JP?  (no BOM)
Shunt SMT
footprint SHUNT_SMT
pins: 1, 2

## SIP-2
designator JP?
2 contact jumper
footprint SIP-2 (0.1 inch Jumper)
pins: 1, 2

## SIP-3
designator J?
3 contact jumper
footprint SIP-3 (3 possition jumper; pitch 0.1")
pins: 1, 2, 3

## SIP-3_Jumper
designator JP?
3 contact jumper
footprint SIP-3 (3 possition jumper; pitch 0.1")
pins: 1, 2, 3

## SIP-4
designator JP?
3 contact jumper
footprint SIP-4 (Header; 4pin; pitch 0.1")
pins: 1, 2, 3, 4

## SIP-5
designator J?
5 Pin; 0.1" (2.54mm); Single Row; Header
footprint SIP-5 (Header; 5 pin; pitch 0.1")
pins: 1, 2, 3, 4, 5

## SIP-6
designator CN?
6 Pin; 0.1" (2.54mm); Single Row; Header
footprint SIP-6 (Header, 6 pin, pitch 0.1")
pins: 1, 2, 3, 4, 5, 6

## SIP-6_2mm
designator CN?
6 Pin; 0.1" (2.0mm); Single Row; Male Header; Right Angle
footprint SIP-6-2mm (Header, 6 pin, pitch 2.0mm; pin 2 blind; for VII debugger module)
pins: 1, 2, 3, 4, 5, 6

## SIP-7
designator J?
7 Pin; 0.1" (2.54mm); Single Row; Header
footprint SIP-6 (Header, 6 pin, pitch 0.1")
pins: 1, 2, 3, 4, 5, 6, 7

## SIP-8
designator CN?
8 Pin; 0.1" (2.54mm); Single Row; Header
footprint SIP-6 (Header, 6 pin, pitch 0.1")
pins: 1, 2, 3, 4, 5, 6, 7, 8

## SIP-20
designator CN?
20 Pin; Single Row; Header
footprint SIP-20
pins: 1, 2, 3, 4, 5, 6, 7, 8, 9, 10, 11, 12, 13, 14, 15, 16, 17, 18, 19, 20

## SKT_QFP-48
designator SKT?, comment LQFP-48-TEST_AND_BURN_SOCKET  (mechanical)
QFP Clamshell Socket; IC51-0484-806; YAMAICHI
footprint TQFP48_CLAMSHELL_FIX (YAMAICHI IC51-0484-806 WITH FIXING HOLES)

## SKT_SD_Card
designator SKT?, comment 48000-2001
SD/Memory Stick Card socket, Molex
footprint SKT_SD_CARD
pins: 1 MS1 hidden, 2 MS2 hidden, 3 MS3 hidden, 4 MS4 hidden, 5 MS5 hidden, 6 MS6 hidden, 7 MS7 hidden, 8 MS8 hidden, 9 MS9 hidden, 10 MS10 hidden, 11 SD1, 12 SD2, 13 SD3, 14 SD4, 15 SD5, 16 SD6, 17 SD7, 18 SD8, 19 SD9, 20 COM, 21 DET, 22 LOCK, 23 NC

## SN74LVC2T45DCUR
designator U*
footprint TSSOP50P310X110-8N (TSSOP, 8-Leads, Body 2.0x2.3mm (max), Pitch 0.50mm, IPC Medium Density)
pins: 1 VCCA, 2 A1, 3 A2, 4 GND, 5 DIR, 6 B2, 7 B1, 8 VCCB

## SPEAKER
designator SP?
Speaker 8-ohm 1.5W
pins: 1 + "+ve", 2 - "-ve"

## SW-DPDT_G3T22AB
designator SW?, comment G3T22AB
Process Sealed Ultra-Miniature SMT Toggle Switch; DPDT
footprint SW_EG1271 (Switch; SPDT; E Switch EG1271A)
footprint SW_G3T22AB-NKK Switches (Switch; DPDT; Process Sealed Ultra-Miniature SMT Toggle Switch)
pins: 1, 2, 3, 4, 5, 6, 7

## SW-KPS-1290
designator SW?
Switch
footprint SW_EB800_PWR_SW
pins: 1, 2, 3, 4 hidden

## SW-NAVI_TMHU13
designator SW?, comment TMHU13
Navigation switch with select
footprint SW_PushButton
footprint SW_NAVIGATION_TMNU13 (TMHU13 navigation switch (joystick))
pins: 1 U, 2 SEL, 3 L, 4 R, 5 COM, 6 D, 7 SHLD, 8 SHLD

## SW-PB_ILUM
designator SW?, comment SW_PB
Push button momentary switch
footprint SW_PushButton
footprint SW_TL1240_ESwitch
pins: 1, 2, 3 K, 4 A

## SW-SPDT
designator SW?
SPDT Switch
footprint SW_EG1271 (Switch; SPDT; E Switch EG1271A)
footprint SW_500ASSP1M2 (500A series; Sub-Minature; Slide Switch;SP-DT; E-Switch)
pins: 1, 2, 3, 4, 5, 6

## SW-TL3200AF160GRQ
designator SW?, comment SW_PB
Tactile switch with green/red LEDs; Manufacturer: E-Switch; ManufacturerPartNo: TL3200AF160GRQ; Note: SWITCH TACTILE SPST-NO 0.05A 12V
footprint SW_PushButton
footprint SW_TL1240_ESwitch
pins: 1, 2, 3 A, 4 K, 5 A, 6 K

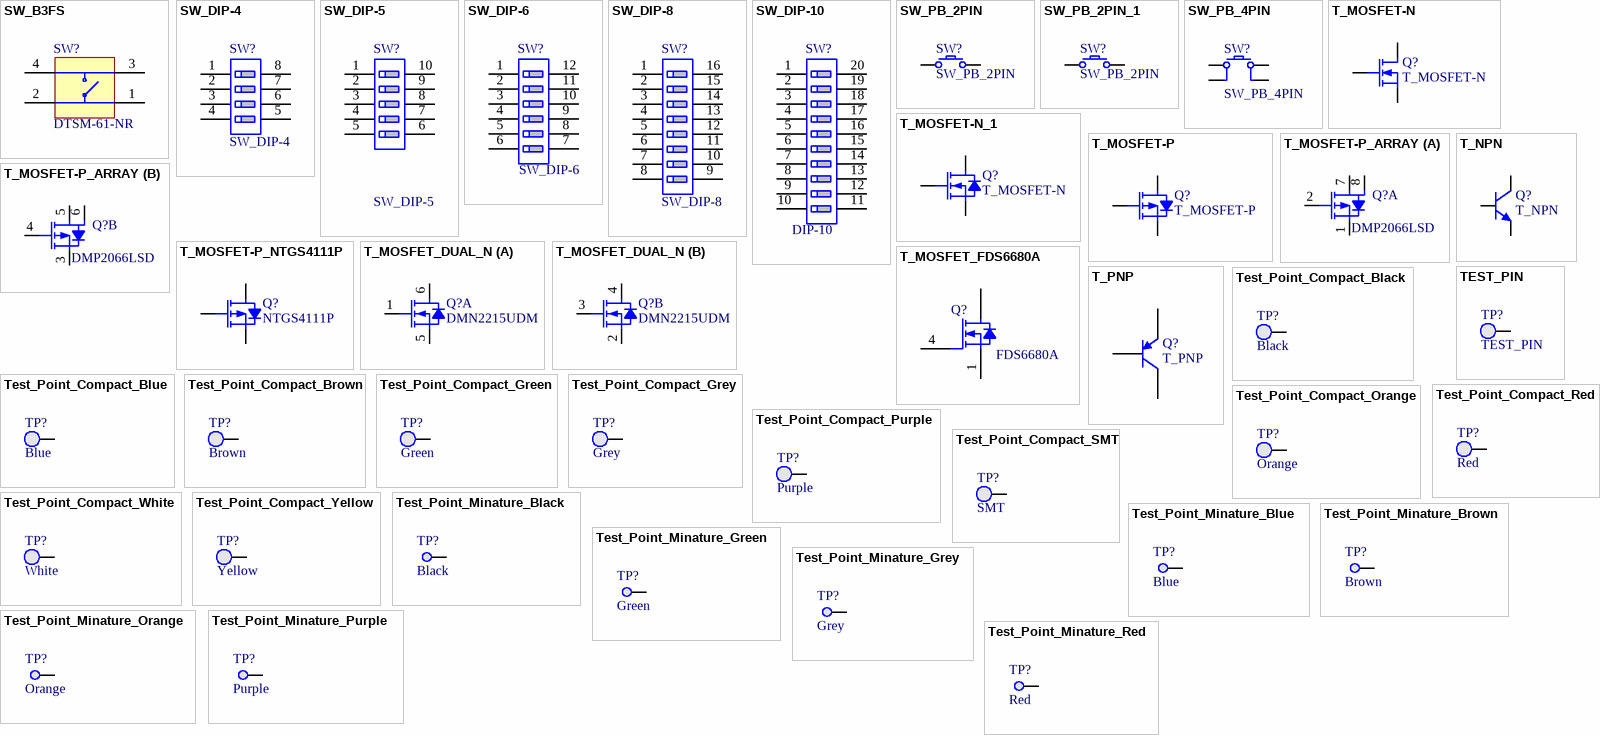
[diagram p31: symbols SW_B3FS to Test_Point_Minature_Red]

## SW_B3FS
designator SW?, comment DTSM-61-NR
SPNA SMD Keyboard Switch
footprint B3FS_SWITCH
pins: 1, 2, 3, 4

## SW_DIP-4
designator SW?
DIP Switch, 4 Position, SPST
footprint SW_DIP-4_SMT (DIP Switch; SMT)
pins: 1 A1, 2 A2, 3 A3, 4 A4, 5 A5, 6 A6, 7 A7, 8 A8

## SW_DIP-5
designator SW?
DIP Switch, 5 possitions
pins: 1 A1, 2 A2, 3 A3, 4 A4, 5 A5, 6 B5, 7 B4, 8 B3, 9 B2, 10 B1

## SW_DIP-6
designator SW?
DIP Switch, 8 possitions
footprint SW_DIP_TDA06H0SB1 (DIP Switch; Half pitch (1.27mm); 6 possitions; C&K; TDA06H0SB1)
pins: 1 A1, 2 A2, 3 A3, 4 A4, 5 A5, 6 A6, 7 A7, 8 A8, 9 B8, 10 B7, 11 B6, 12 B5

## SW_DIP-8
designator SW?
DIP Switch, 8 possitions
pins: 1 A1, 2 A2, 3 A3, 4 A4, 5 A5, 6 A6, 7 A7, 8 A8, 9 B8, 10 B7, 11 B6, 12 B5, 13 B4, 14 B3, 15 B2, 16 B1

## SW_DIP-10
designator SW?, comment DIP-10
DIP Switch, 10 possitions
footprint SW_DIP_TDA10H0SB1 (DIP Switch; Half pitch (1.27mm); 10 possitions; C&K; TDA10H0SB1)
pins: 1 A1, 2 A2, 3 A3, 4 A4, 5 A5, 6 A6, 7 A7, 8 A8, 9 A9, 10 A10, 11 B10, 12 B9, 13 B8, 14 B7, 15 B6, 16 B5, 17 B4, 18 B3, 19 B2, 20 B1

## SW_PB_2PIN
designator SW?
Push button momentary switch
footprint SW_PushButton
footprint SW_Multimex_3E (TL6120, Sealed SMT Tacctile Switch; E-Switch)
pins: 1, 2

## SW_PB_2PIN_1
designator SW?, comment SW_PB_2PIN
Push button momentary switch
footprint SW_PushButton
footprint SW_Multimex_3E (TL6120, Sealed SMT Tacctile Switch; E-Switch)
pins: A, B

## SW_PB_4PIN
designator SW?
Push button momentary switch
footprint SW_PushButton
footprint SW_Multimex_3E (TL6120, Sealed SMT Tacctile Switch; E-Switch)
pins: 1, 2, 3, 4

## T_MOSFET-N
designator Q?
N-Channel MOSFET
simulation model NMOS (MOSFET-N)
footprint SOT23-3AL
pins: 1 G, 2 S, 3 D

## T_MOSFET-N_1
designator Q?, comment T_MOSFET-N
N-Channel MOSFET; SOT-23
simulation model PMOS (MOSFET-P)
footprint SOT23-3AL
pins: 1 G, 2 S, 3 D

## T_MOSFET-P
designator Q?
P-Channel MOSFET; SOT-23
simulation model PMOS (MOSFET-P)
footprint SOT23-3AL
pins: 1 G, 2 S, 3 D

## T_MOSFET-P_ARRAY
designator Q?, comment DMP2066LSD
DUAL P-CHANNEL ENHANCEMENT MODE MOSFET
simulation model PMOS (MOSFET-P)
footprint SO-8N (8-Pin Small Outline Integrated Circuit 1.27 mm Pitch, IPC Medium Density)
part A pins: 1 S1, 2 G1, 7 D1, 8 D2
part B pins: 3 S2, 4 G2, 5 D2, 6 D2

## T_MOSFET-P_NTGS4111P
designator Q?, comment NTGS4111P
-30 V, -4.7 A, Single P-Channel, TSOP-6; NTGS4111P; On Semiconductor; ManufacturerPartNo: NTGS4111PT1G; Note: MOSFET P-CH 30V 2.6A 6-TSOP
simulation model PMOS (MOSFET-P)
footprint TSOP95P280X110-6N (TSOP, 6-Leads, Body 3.00x1.50mm, Pitch 0.95mm, IPC Medium Density)
pins: 1 D, 2 D, 3 G, 4 S, 5 D, 6 D

## T_MOSFET_DUAL_N
designator Q?, comment DMN2215UDM
N-Channel MOSFET; SOT-23
footprint SOT23-6N (SOT23, 6-Leads, Body 3.0x3.0mm (max), Pitch 0.95mm, IPC Medium Density)
part A pins: 1 G1, 5 S1, 6 D1
part B pins: 2 S2, 3 G2, 4 D2

## T_MOSFET_FDS6680A
designator Q?, comment FDS6680A
N Channel MOSFET in SO-8
footprint SO-8_N (8-Pin Small Outline Integrated Circuit 1.27 mm Pitch, IPC Medium Density)
pins: 1 S, 2 S, 3 S, 4 G, 5 D, 6 D, 7 D, 8 D

## T_NPN
designator Q?
NPN Bipolar Transistor
simulation model NPN
signal-integrity model NPN
footprint SOT23-3AL
pins: 1 B, 2 E, 3 C

## T_PNP
designator Q?
PNP Bipolar Transistor
simulation model PNP
signal-integrity model PNP
footprint SOT23-3AL
pins: 1 B, 2 E, 3 C

## TEST_PIN
designator TP?
Test pin
footprint TEST_PIN_MULTILAYER (Test pin; 0.8mm / 1.6mm, multilayer)
pins: TP

## Test_Point_Compact_Black
designator TP?, comment Black
Test Point; PTH; Compact; Black; Keystone; 5006; Manufacturer: Keystone Electronics; ManufacturerPartNo: 5006; Note: TEST POINT PC COMPACT .063"D BLK
footprint TEST_PIN_MULTILAYER (Test pin; 0.8mm / 1.6mm, multilayer)
pins: TP

## Test_Point_Compact_Blue
designator TP?, comment Blue
Test Point; PTH; Compact; Blue; Keystone; 5122; Manufacturer: Keystone Electronics; ManufacturerPartNo: 5122; Note: TEST POINT PC COMPACT T/H BLUE
footprint TEST_PIN_MULTILAYER (Test pin; 0.8mm / 1.6mm, multilayer)
pins: TP

## Test_Point_Compact_Brown
designator TP?, comment Brown
Test Point; PTH; Compact; Brown; Keystone; 5120; Manufacturer: Keystone Electronics; ManufacturerPartNo: 5120; Note: TEST POINT PC COMPACT T/H BROWN
footprint TEST_PIN_MULTILAYER (Test pin; 0.8mm / 1.6mm, multilayer)
pins: TP

## Test_Point_Compact_Green
designator TP?, comment Green
Test Point; PTH; Compact; White; Keystone; 5121; Manufacturer: Keystone Electronics; ManufacturerPartNo: 5121; Note: TEST POINT PC COMPACT T/H GREEN
footprint TEST_PIN_MULTILAYER (Test pin; 0.8mm / 1.6mm, multilayer)
pins: TP

## Test_Point_Compact_Grey
designator TP?, comment Grey
Test Point; PTH; Compact; Grey; Keystone; 5123; Manufacturer: Keystone Electronics; ManufacturerPartNo: 5123; Note: TEST POINT PC COMPACT T/H GREY
footprint TEST_PIN_MULTILAYER (Test pin; 0.8mm / 1.6mm, multilayer)
pins: TP

## Test_Point_Compact_Orange
designator TP?, comment Orange
Test Point; PTH; Compact; Orange; Keystone; 5008; Manufacturer: Keystone Electronics; ManufacturerPartNo: 5008; Note: TEST POINT PC COMPACT .063"D ORN
footprint TEST_PIN_MULTILAYER (Test pin; 0.8mm / 1.6mm, multilayer)
pins: TP

## Test_Point_Compact_Purple
designator TP?, comment Purple
Test Point; PTH; Compact; Purple; Keystone; 5124; Manufacturer: Keystone Electronics; ManufacturerPartNo: 5124; Note: TEST POINT PC COMPACT T/H PURPLE
footprint TEST_PIN_MULTILAYER (Test pin; 0.8mm / 1.6mm, multilayer)
pins: TP

## Test_Point_Compact_Red
designator TP?, comment Red
Test Point; PTH; Compact; Red; Keystone; 5005; Manufacturer: Keystone Electronics; ManufacturerPartNo: 5005; Note: TEST POINT PC COMPACT .063"D RED
footprint TEST_PIN_MULTILAYER (Test pin; 0.8mm / 1.6mm, multilayer)
pins: TP

## Test_Point_Compact_SMT
designator TP?, comment SMT
Test Point; SMT; Compact; Keystone; 5016; Manufacturer: Keystone Electronics; ManufacturerPartNo: 5016; Note: PC TEST POINT COMPACT SMT
footprint TEST_PIN_MULTILAYER (Test pin; 0.8mm / 1.6mm, multilayer)
pins: TP

## Test_Point_Compact_White
designator TP?, comment White
Test Point; PTH; Compact; White; Keystone; 5007; Manufacturer: Keystone Electronics; ManufacturerPartNo: 5007; Note: TEST POINT PC COMPACT .063"D WHT
footprint TEST_PIN_MULTILAYER (Test pin; 0.8mm / 1.6mm, multilayer)
pins: TP

## Test_Point_Compact_Yellow
designator TP?, comment Yellow
Test Point; PTH; Compact; Yellow; Keystone; 5009; Manufacturer: Keystone Electronics; ManufacturerPartNo: 5009; Note: TEST POINT PC COMPACT .063"D YLW
footprint TEST_PIN_MULTILAYER (Test pin; 0.8mm / 1.6mm, multilayer)
pins: TP

## Test_Point_Minature_Black
designator TP?, comment Black
Test Point; PTH; Minature; Black; Keystone; 5001; Manufacturer: Keystone Electronics; ManufacturerPartNo: 5001; Note: TEST POINT PC MINI .040"D BLACK
footprint TEST_PIN_MULTILAYER (Test pin; 0.8mm / 1.6mm, multilayer)
pins: TP

## Test_Point_Minature_Blue
designator TP?, comment Blue
Test Point; PTH; Minature; Blue; Keystone; 5117; Manufacturer: Keystone Electronics; ManufacturerPartNo: 5117; Note: TEST POINT PC MINIATURE T/H BLUE
footprint TEST_PIN_MULTILAYER (Test pin; 0.8mm / 1.6mm, multilayer)
pins: TP

## Test_Point_Minature_Brown
designator TP?, comment Brown
Test Point; PTH; Minature; Red; Keystone; 5115; Manufacturer: Keystone Electronics; ManufacturerPartNo: 5115; Note: TEST POINT PC MINIATURE T/H BRWN
footprint TEST_PIN_MULTILAYER (Test pin; 0.8mm / 1.6mm, multilayer)
pins: TP

## Test_Point_Minature_Green
designator TP?, comment Green
Test Point; PTH; Minature; Green; Keystone; 5116; Manufacturer: Keystone Electronics; ManufacturerPartNo: 5116; Note: TEST POINT PC MINIATURE T/H GRN
footprint TEST_PIN_MULTILAYER (Test pin; 0.8mm / 1.6mm, multilayer)
pins: TP

## Test_Point_Minature_Grey
designator TP?, comment Grey
Test Point; PTH; Minature; Grey; Keystone; 5118; Manufacturer: Keystone Electronics; ManufacturerPartNo: 5118; Note: TEST POINT PC MINIATURE T/H GREY
footprint TEST_PIN_MULTILAYER (Test pin; 0.8mm / 1.6mm, multilayer)
pins: TP

## Test_Point_Minature_Orange
designator TP?, comment Orange
Test Point; PTH; Minature; Red; Keystone; 5003; Manufacturer: Keystone Electronics; ManufacturerPartNo: 5003; Note: TEST POINT PC MINI .040"D ORANGE
footprint TEST_PIN_MULTILAYER (Test pin; 0.8mm / 1.6mm, multilayer)
pins: TP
